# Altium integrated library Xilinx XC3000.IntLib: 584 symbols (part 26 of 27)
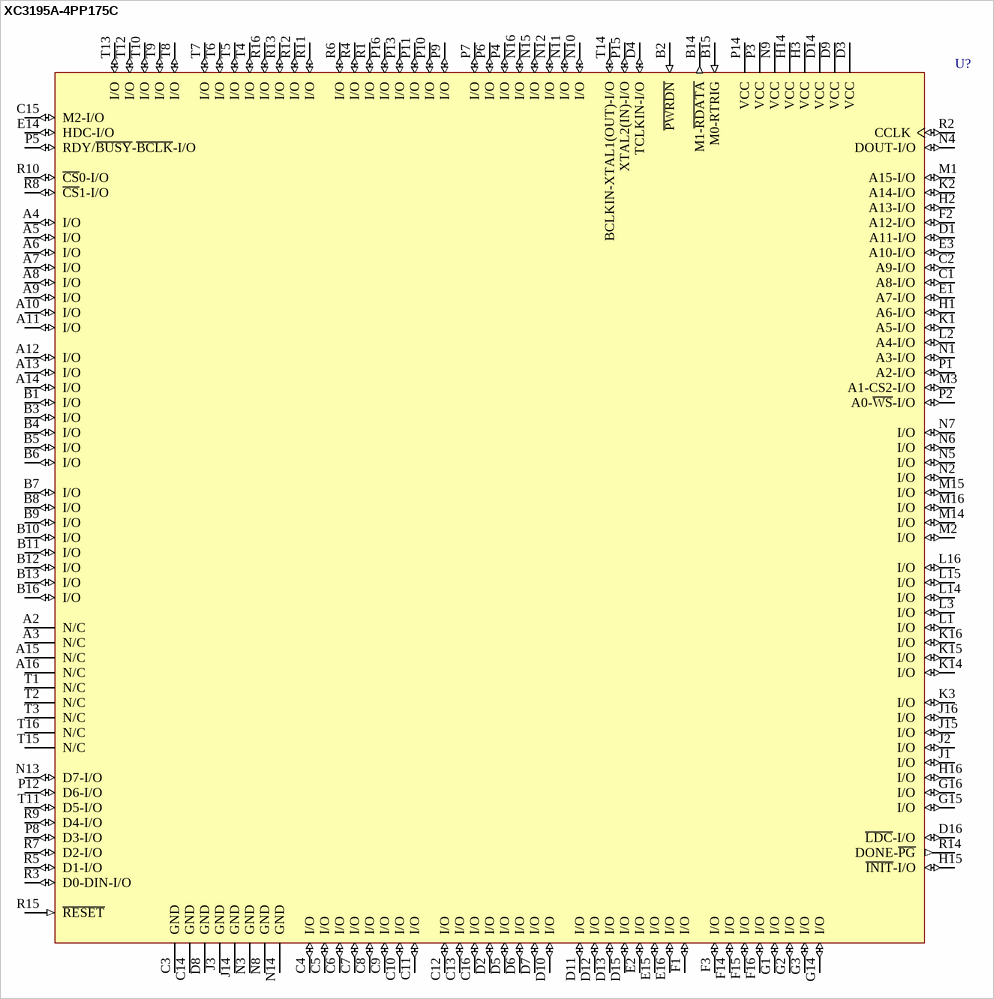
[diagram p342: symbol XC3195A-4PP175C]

## XC3195A-4PP175C
designator U?
Logic Cell Array with 484 CLBs, with 144 I/O Pins, 175-Pin PGA, Commercial Grade; ComponentAvailability: Not for New Design
footprint PP175 (PGA, 175-Leads, Body 42x42mm, Pitch 2.54mm)
3D model XC3195A-PP175 (175-Pin Plastic Pin Grid Array (PP175))
pins: A2 N/C, A3 N/C, A4 I/O (io), A5 I/O (io), A6 I/O (io), A7 I/O (io), A8 I/O (io), A9 I/O (io), A10 I/O (io), A11 I/O (io), A12 I/O (io), A13 I/O (io), A14 I/O (io), A15 N/C, A16 N/C, B1 I/O (io), B2 ~{PWRDN} (in), B3 I/O (io), B4 I/O (io), B5 I/O (io), B6 I/O (io), B7 I/O (io), B8 I/O (io), B9 I/O (io), B10 I/O (io), B11 I/O (io), B12 I/O (io), B13 I/O (io), B14 M1-~{RDATA} (out), B15 M0-RTRIG (in), B16 I/O (io), C1 A8-I/O (io), C2 A9-I/O (io), C3 GND (power), C4 I/O (io), C5 I/O (io), C6 I/O (io), C7 I/O (io), C8 I/O (io), C9 I/O (io), C10 I/O (io), C11 I/O (io), C12 I/O (io), C13 I/O (io), C14 GND (power), C15 M2-I/O (io), C16 I/O (io), D1 A11-I/O (io), D2 I/O (io), D3 VCC (power), D4 TCLKIN-I/O (io), D5 I/O (io), D6 I/O (io), D7 I/O (io), D8 GND (power), D9 VCC (power), D10 I/O (io), D11 I/O (io), D12 I/O (io), D13 I/O (io), D14 VCC (power), D15 I/O (io), D16 ~{LDC}-I/O (io), E1 A7-I/O (io), E2 I/O (io), E3 A10-I/O (io), E14 HDC-I/O (io), E15 I/O (io), E16 I/O (io), F1 I/O (io), F2 A12-I/O (io), F3 I/O (io), F14 I/O (io), F15 I/O (io), F16 I/O (io), G1 I/O (io), G2 I/O (io), G3 I/O (io), G14 I/O (io), G15 I/O (io), G16 I/O (io), H1 A6-I/O (io), H2 A13-I/O (io), H3 VCC (power), H14 VCC (power), H15 ~{INIT}-I/O (io), H16 I/O (io), J1 I/O (io), J2 I/O (io), J3 GND (power), J14 GND (power), J15 I/O (io), J16 I/O (io), K1 A5-I/O (io), K2 A14-I/O (io), K3 I/O (io), K14 I/O (io), K15 I/O (io), K16 I/O (io), L1 I/O (io), L2 A4-I/O (io), L3 I/O (io), L14 I/O (io), L15 I/O (io), L16 I/O (io), M1 A15-I/O (io), M2 I/O (io), M3 A1-CS2-I/O (io), M14 I/O (io), M15 I/O (io), M16 I/O (io), N1 A3-I/O (io), N2 I/O (io), N3 GND (power), N4 DOUT-I/O (io), N5 I/O (io), N6 I/O (io), N7 I/O (io), N8 GND (power), N9 VCC (power), N10 I/O (io), N11 I/O (io), N12 I/O (io), N13 D7-I/O (io), N14 GND (power), N15 I/O (io), N16 I/O (io), P1 A2-I/O (io), P2 A0-~{WS}-I/O (io), P3 VCC (power), P4 I/O (io), P5 RDY/~{BUSY}-~{BCLK}-I/O (io), P6 I/O (io), P7 I/O (io), P8 D3-I/O (io), P9 I/O (io), P10 I/O (io), P11 I/O (io), P12 D6-I/O (io), P13 I/O (io), P14 VCC (power), P15 XTAL2(IN)-I/O (io), P16 I/O (io), R1 I/O (io), R2 CCLK (io), R3 D0-DIN-I/O (io), R4 I/O (io), R5 D1-I/O (io), R6 I/O (io), R7 D2-I/O (io), R8 ~{CS}1-I/O (io), R9 D4-I/O (io), R10 ~{CS}0-I/O (io), R11 I/O (io), R12 I/O (io), R13 I/O (io), R14 DONE-~{PG} (out), R15 ~{RESET} (in), R16 I/O (io), T1 N/C, T2 N/C, T3 N/C, T4 I/O (io), T5 I/O (io), T6 I/O (io), T7 I/O (io), T8 I/O (io), T9 I/O (io), T10 I/O (io), T11 D5-I/O (io), T12 I/O (io), T13 I/O (io), T14 BCLKIN-XTAL1(OUT)-I/O (io), T15 N/C, T16 N/C

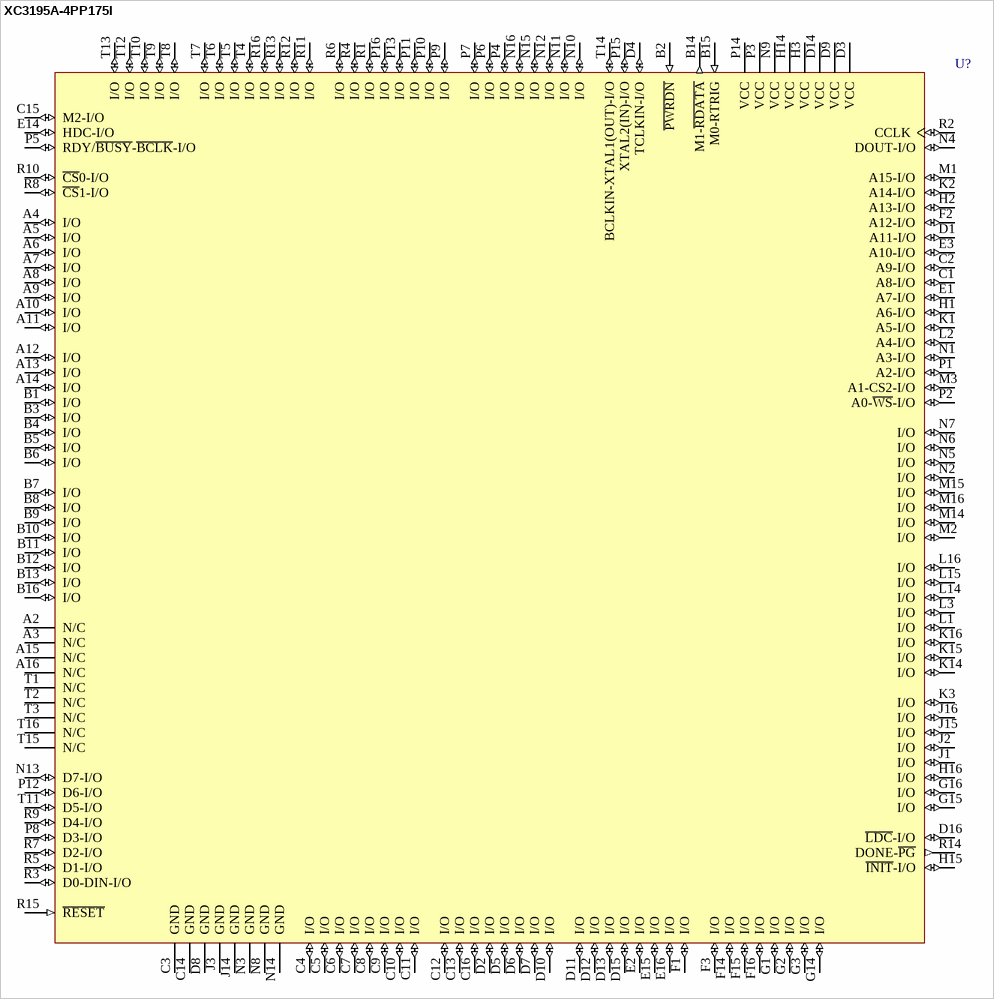
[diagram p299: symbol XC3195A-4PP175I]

## XC3195A-4PP175I
designator U?
Logic Cell Array with 484 CLBs, with 144 I/O Pins, 175-Pin PGA, Industrial Grade; ComponentAvailability: Not for New Design
footprint PP175 (PGA, 175-Leads, Body 42x42mm, Pitch 2.54mm)
3D model XC3195A-PP175 (175-Pin Plastic Pin Grid Array (PP175))
pins: A2 N/C, A3 N/C, A4 I/O (io), A5 I/O (io), A6 I/O (io), A7 I/O (io), A8 I/O (io), A9 I/O (io), A10 I/O (io), A11 I/O (io), A12 I/O (io), A13 I/O (io), A14 I/O (io), A15 N/C, A16 N/C, B1 I/O (io), B2 ~{PWRDN} (in), B3 I/O (io), B4 I/O (io), B5 I/O (io), B6 I/O (io), B7 I/O (io), B8 I/O (io), B9 I/O (io), B10 I/O (io), B11 I/O (io), B12 I/O (io), B13 I/O (io), B14 M1-~{RDATA} (out), B15 M0-RTRIG (in), B16 I/O (io), C1 A8-I/O (io), C2 A9-I/O (io), C3 GND (power), C4 I/O (io), C5 I/O (io), C6 I/O (io), C7 I/O (io), C8 I/O (io), C9 I/O (io), C10 I/O (io), C11 I/O (io), C12 I/O (io), C13 I/O (io), C14 GND (power), C15 M2-I/O (io), C16 I/O (io), D1 A11-I/O (io), D2 I/O (io), D3 VCC (power), D4 TCLKIN-I/O (io), D5 I/O (io), D6 I/O (io), D7 I/O (io), D8 GND (power), D9 VCC (power), D10 I/O (io), D11 I/O (io), D12 I/O (io), D13 I/O (io), D14 VCC (power), D15 I/O (io), D16 ~{LDC}-I/O (io), E1 A7-I/O (io), E2 I/O (io), E3 A10-I/O (io), E14 HDC-I/O (io), E15 I/O (io), E16 I/O (io), F1 I/O (io), F2 A12-I/O (io), F3 I/O (io), F14 I/O (io), F15 I/O (io), F16 I/O (io), G1 I/O (io), G2 I/O (io), G3 I/O (io), G14 I/O (io), G15 I/O (io), G16 I/O (io), H1 A6-I/O (io), H2 A13-I/O (io), H3 VCC (power), H14 VCC (power), H15 ~{INIT}-I/O (io), H16 I/O (io), J1 I/O (io), J2 I/O (io), J3 GND (power), J14 GND (power), J15 I/O (io), J16 I/O (io), K1 A5-I/O (io), K2 A14-I/O (io), K3 I/O (io), K14 I/O (io), K15 I/O (io), K16 I/O (io), L1 I/O (io), L2 A4-I/O (io), L3 I/O (io), L14 I/O (io), L15 I/O (io), L16 I/O (io), M1 A15-I/O (io), M2 I/O (io), M3 A1-CS2-I/O (io), M14 I/O (io), M15 I/O (io), M16 I/O (io), N1 A3-I/O (io), N2 I/O (io), N3 GND (power), N4 DOUT-I/O (io), N5 I/O (io), N6 I/O (io), N7 I/O (io), N8 GND (power), N9 VCC (power), N10 I/O (io), N11 I/O (io), N12 I/O (io), N13 D7-I/O (io), N14 GND (power), N15 I/O (io), N16 I/O (io), P1 A2-I/O (io), P2 A0-~{WS}-I/O (io), P3 VCC (power), P4 I/O (io), P5 RDY/~{BUSY}-~{BCLK}-I/O (io), P6 I/O (io), P7 I/O (io), P8 D3-I/O (io), P9 I/O (io), P10 I/O (io), P11 I/O (io), P12 D6-I/O (io), P13 I/O (io), P14 VCC (power), P15 XTAL2(IN)-I/O (io), P16 I/O (io), R1 I/O (io), R2 CCLK (io), R3 D0-DIN-I/O (io), R4 I/O (io), R5 D1-I/O (io), R6 I/O (io), R7 D2-I/O (io), R8 ~{CS}1-I/O (io), R9 D4-I/O (io), R10 ~{CS}0-I/O (io), R11 I/O (io), R12 I/O (io), R13 I/O (io), R14 DONE-~{PG} (out), R15 ~{RESET} (in), R16 I/O (io), T1 N/C, T2 N/C, T3 N/C, T4 I/O (io), T5 I/O (io), T6 I/O (io), T7 I/O (io), T8 I/O (io), T9 I/O (io), T10 I/O (io), T11 D5-I/O (io), T12 I/O (io), T13 I/O (io), T14 BCLKIN-XTAL1(OUT)-I/O (io), T15 N/C, T16 N/C

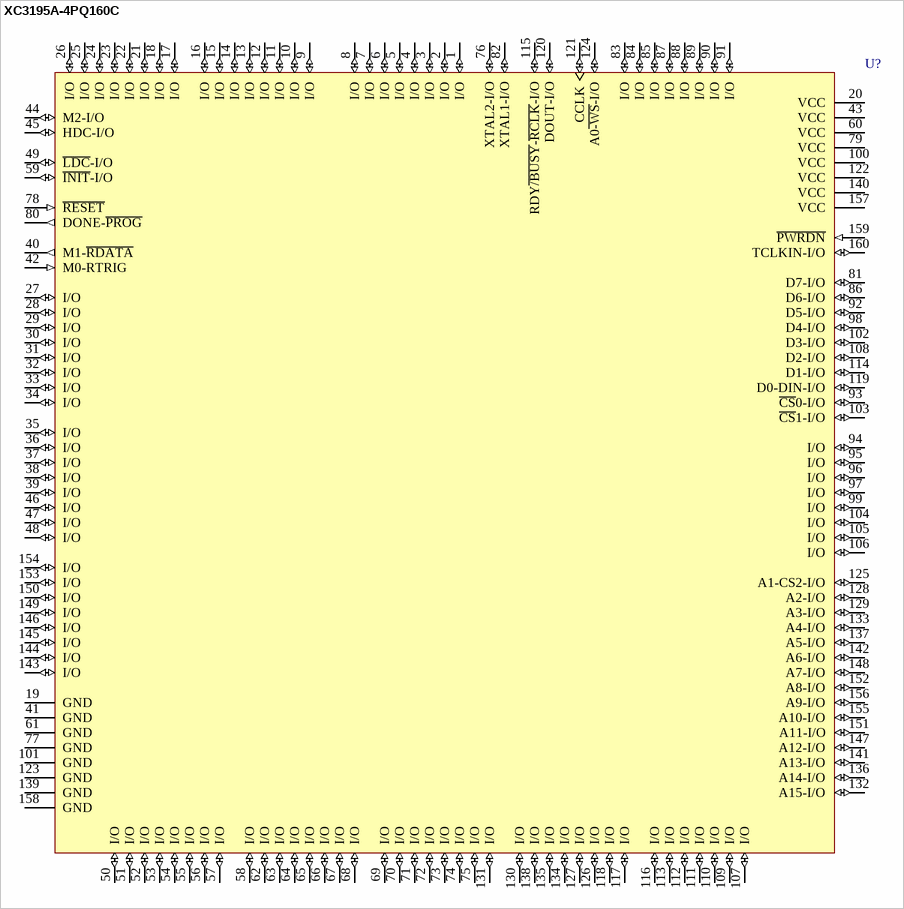
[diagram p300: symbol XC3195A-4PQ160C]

## XC3195A-4PQ160C
designator U?
Logic Cell Array with 484 CLBs, with 138 I/O Pins, 160-Pin PQFP, Commercial Grade; ComponentAvailability: Not for New Design
footprint PQ160_N (QFP, 160-Leads, Body 28 x 28mm, Pitch 0.65mm, IPC Medium Density)
footprint PQ160_L (QFP, 160-Leads, Body 28 x 28mm, Pitch 0.65mm, IPC High Density)
footprint PQ160_M (QFP, 160-Leads, Body 28 x 28mm, Pitch 0.65mm, IPC Low Density)
3D model XC3195A-PQ160 (160-Pin Plastic Quad Flat Pack (PQ160))
pins: 1 I/O (io), 2 I/O (io), 3 I/O (io), 4 I/O (io), 5 I/O (io), 6 I/O (io), 7 I/O (io), 8 I/O (io), 9 I/O (io), 10 I/O (io), 11 I/O (io), 12 I/O (io), 13 I/O (io), 14 I/O (io), 15 I/O (io), 16 I/O (io), 17 I/O (io), 18 I/O (io), 19 GND (power), 20 VCC (power), 21 I/O (io), 22 I/O (io), 23 I/O (io), 24 I/O (io), 25 I/O (io), 26 I/O (io), 27 I/O (io), 28 I/O (io), 29 I/O (io), 30 I/O (io), 31 I/O (io), 32 I/O (io), 33 I/O (io), 34 I/O (io), 35 I/O (io), 36 I/O (io), 37 I/O (io), 38 I/O (io), 39 I/O (io), 40 M1-~{RDATA} (out), 41 GND (power), 42 M0-RTRIG (in), 43 VCC (power), 44 M2-I/O (io), 45 HDC-I/O (io), 46 I/O (io), 47 I/O (io), 48 I/O (io), 49 ~{LDC}-I/O (io), 50 I/O (io), 51 I/O (io), 52 I/O (io), 53 I/O (io), 54 I/O (io), 55 I/O (io), 56 I/O (io), 57 I/O (io), 58 I/O (io), 59 ~{INIT}-I/O (io), 60 VCC (power), 61 GND (power), 62 I/O (io), 63 I/O (io), 64 I/O (io), 65 I/O (io), 66 I/O (io), 67 I/O (io), 68 I/O (io), 69 I/O (io), 70 I/O (io), 71 I/O (io), 72 I/O (io), 73 I/O (io), 74 I/O (io), 75 I/O (io), 76 XTAL2-I/O (io), 77 GND (power), 78 ~{RESET} (in), 79 VCC (power), 80 DONE-~{PROG} (out), 81 D7-I/O (io), 82 XTAL1-I/O (io), 83 I/O (io), 84 I/O (io), 85 I/O (io), 86 D6-I/O (io), 87 I/O (io), 88 I/O (io), 89 I/O (io), 90 I/O (io), 91 I/O (io), 92 D5-I/O (io), 93 ~{CS}0-I/O (io), 94 I/O (io), 95 I/O (io), 96 I/O (io), 97 I/O (io), 98 D4-I/O (io), 99 I/O (io), 100 VCC (power), 101 GND (power), 102 D3-I/O (io), 103 ~{CS}1-I/O (io), 104 I/O (io), 105 I/O (io), 106 I/O (io), 107 I/O (io), 108 D2-I/O (io), 109 I/O (io), 110 I/O (io), 111 I/O (io), 112 I/O (io), 113 I/O (io), 114 D1-I/O (io), 115 RDY~{/BUSY}-~{RCLK}-I/O (io), 116 I/O (io), 117 I/O (io), 118 I/O (io), 119 D0-DIN-I/O (io), 120 DOUT-I/O (io), 121 CCLK (io), 122 VCC (power), 123 GND (power), 124 A0~{-WS}-I/O (io), 125 A1-CS2-I/O (io), 126 I/O (io), 127 I/O (io), 128 A2-I/O (io), 129 A3-I/O (io), 130 I/O (io), 131 I/O (io), 132 A15-I/O (io), 133 A4-I/O (io), 134 I/O (io), 135 I/O (io), 136 A14-I/O (io), 137 A5-I/O (io), 138 I/O (io), 139 GND (power), 140 VCC (power), 141 A13-I/O (io), 142 A6-I/O (io), 143 I/O (io), 144 I/O (io), 145 I/O (io), 146 I/O (io), 147 A12-I/O (io), 148 A7-I/O (io), 149 I/O (io), 150 I/O (io), 151 A11-I/O (io), 152 A8-I/O (io), 153 I/O (io), 154 I/O (io), 155 A10-I/O (io), 156 A9-I/O (io), 157 VCC (power), 158 GND (power), 159 ~{PWRDN} (in), 160 TCLKIN-I/O (io)

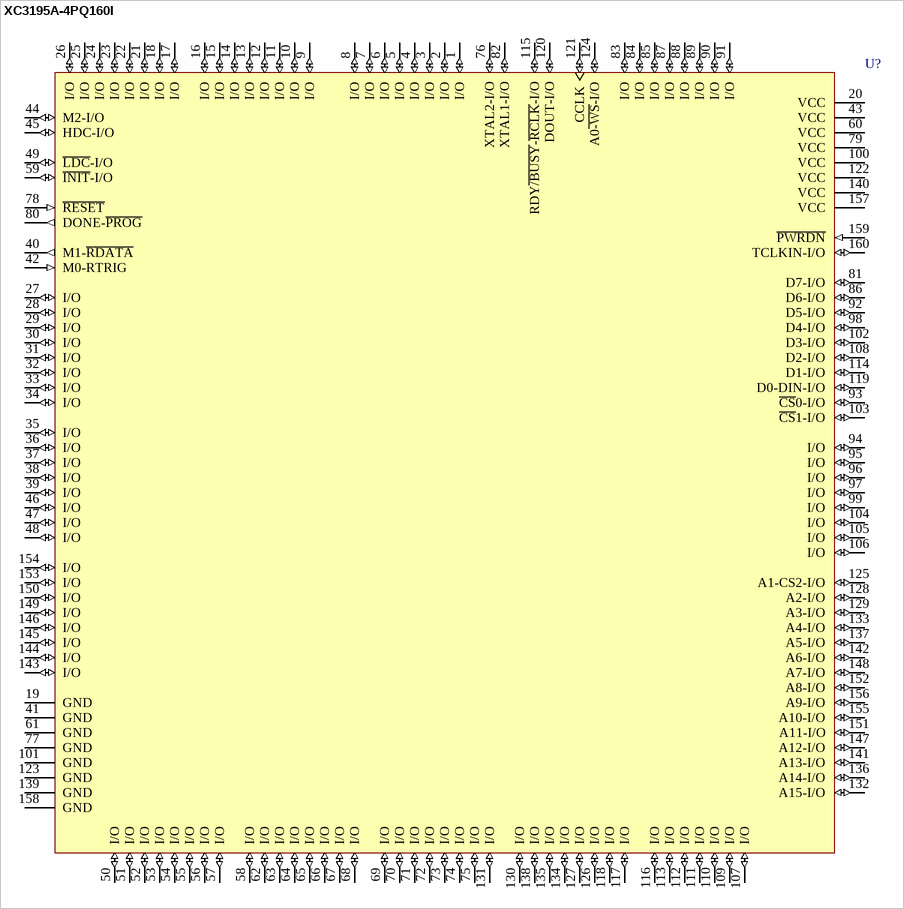
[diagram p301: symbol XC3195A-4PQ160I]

## XC3195A-4PQ160I
designator U?
Logic Cell Array with 484 CLBs, with 138 I/O Pins, 160-Pin PQFP, Industrial Grade; ComponentAvailability: Not for New Design
footprint PQ160_N (QFP, 160-Leads, Body 28 x 28mm, Pitch 0.65mm, IPC Medium Density)
footprint PQ160_L (QFP, 160-Leads, Body 28 x 28mm, Pitch 0.65mm, IPC High Density)
footprint PQ160_M (QFP, 160-Leads, Body 28 x 28mm, Pitch 0.65mm, IPC Low Density)
3D model XC3195A-PQ160 (160-Pin Plastic Quad Flat Pack (PQ160))
pins: 1 I/O (io), 2 I/O (io), 3 I/O (io), 4 I/O (io), 5 I/O (io), 6 I/O (io), 7 I/O (io), 8 I/O (io), 9 I/O (io), 10 I/O (io), 11 I/O (io), 12 I/O (io), 13 I/O (io), 14 I/O (io), 15 I/O (io), 16 I/O (io), 17 I/O (io), 18 I/O (io), 19 GND (power), 20 VCC (power), 21 I/O (io), 22 I/O (io), 23 I/O (io), 24 I/O (io), 25 I/O (io), 26 I/O (io), 27 I/O (io), 28 I/O (io), 29 I/O (io), 30 I/O (io), 31 I/O (io), 32 I/O (io), 33 I/O (io), 34 I/O (io), 35 I/O (io), 36 I/O (io), 37 I/O (io), 38 I/O (io), 39 I/O (io), 40 M1-~{RDATA} (out), 41 GND (power), 42 M0-RTRIG (in), 43 VCC (power), 44 M2-I/O (io), 45 HDC-I/O (io), 46 I/O (io), 47 I/O (io), 48 I/O (io), 49 ~{LDC}-I/O (io), 50 I/O (io), 51 I/O (io), 52 I/O (io), 53 I/O (io), 54 I/O (io), 55 I/O (io), 56 I/O (io), 57 I/O (io), 58 I/O (io), 59 ~{INIT}-I/O (io), 60 VCC (power), 61 GND (power), 62 I/O (io), 63 I/O (io), 64 I/O (io), 65 I/O (io), 66 I/O (io), 67 I/O (io), 68 I/O (io), 69 I/O (io), 70 I/O (io), 71 I/O (io), 72 I/O (io), 73 I/O (io), 74 I/O (io), 75 I/O (io), 76 XTAL2-I/O (io), 77 GND (power), 78 ~{RESET} (in), 79 VCC (power), 80 DONE-~{PROG} (out), 81 D7-I/O (io), 82 XTAL1-I/O (io), 83 I/O (io), 84 I/O (io), 85 I/O (io), 86 D6-I/O (io), 87 I/O (io), 88 I/O (io), 89 I/O (io), 90 I/O (io), 91 I/O (io), 92 D5-I/O (io), 93 ~{CS}0-I/O (io), 94 I/O (io), 95 I/O (io), 96 I/O (io), 97 I/O (io), 98 D4-I/O (io), 99 I/O (io), 100 VCC (power), 101 GND (power), 102 D3-I/O (io), 103 ~{CS}1-I/O (io), 104 I/O (io), 105 I/O (io), 106 I/O (io), 107 I/O (io), 108 D2-I/O (io), 109 I/O (io), 110 I/O (io), 111 I/O (io), 112 I/O (io), 113 I/O (io), 114 D1-I/O (io), 115 RDY~{/BUSY}-~{RCLK}-I/O (io), 116 I/O (io), 117 I/O (io), 118 I/O (io), 119 D0-DIN-I/O (io), 120 DOUT-I/O (io), 121 CCLK (io), 122 VCC (power), 123 GND (power), 124 A0~{-WS}-I/O (io), 125 A1-CS2-I/O (io), 126 I/O (io), 127 I/O (io), 128 A2-I/O (io), 129 A3-I/O (io), 130 I/O (io), 131 I/O (io), 132 A15-I/O (io), 133 A4-I/O (io), 134 I/O (io), 135 I/O (io), 136 A14-I/O (io), 137 A5-I/O (io), 138 I/O (io), 139 GND (power), 140 VCC (power), 141 A13-I/O (io), 142 A6-I/O (io), 143 I/O (io), 144 I/O (io), 145 I/O (io), 146 I/O (io), 147 A12-I/O (io), 148 A7-I/O (io), 149 I/O (io), 150 I/O (io), 151 A11-I/O (io), 152 A8-I/O (io), 153 I/O (io), 154 I/O (io), 155 A10-I/O (io), 156 A9-I/O (io), 157 VCC (power), 158 GND (power), 159 ~{PWRDN} (in), 160 TCLKIN-I/O (io)

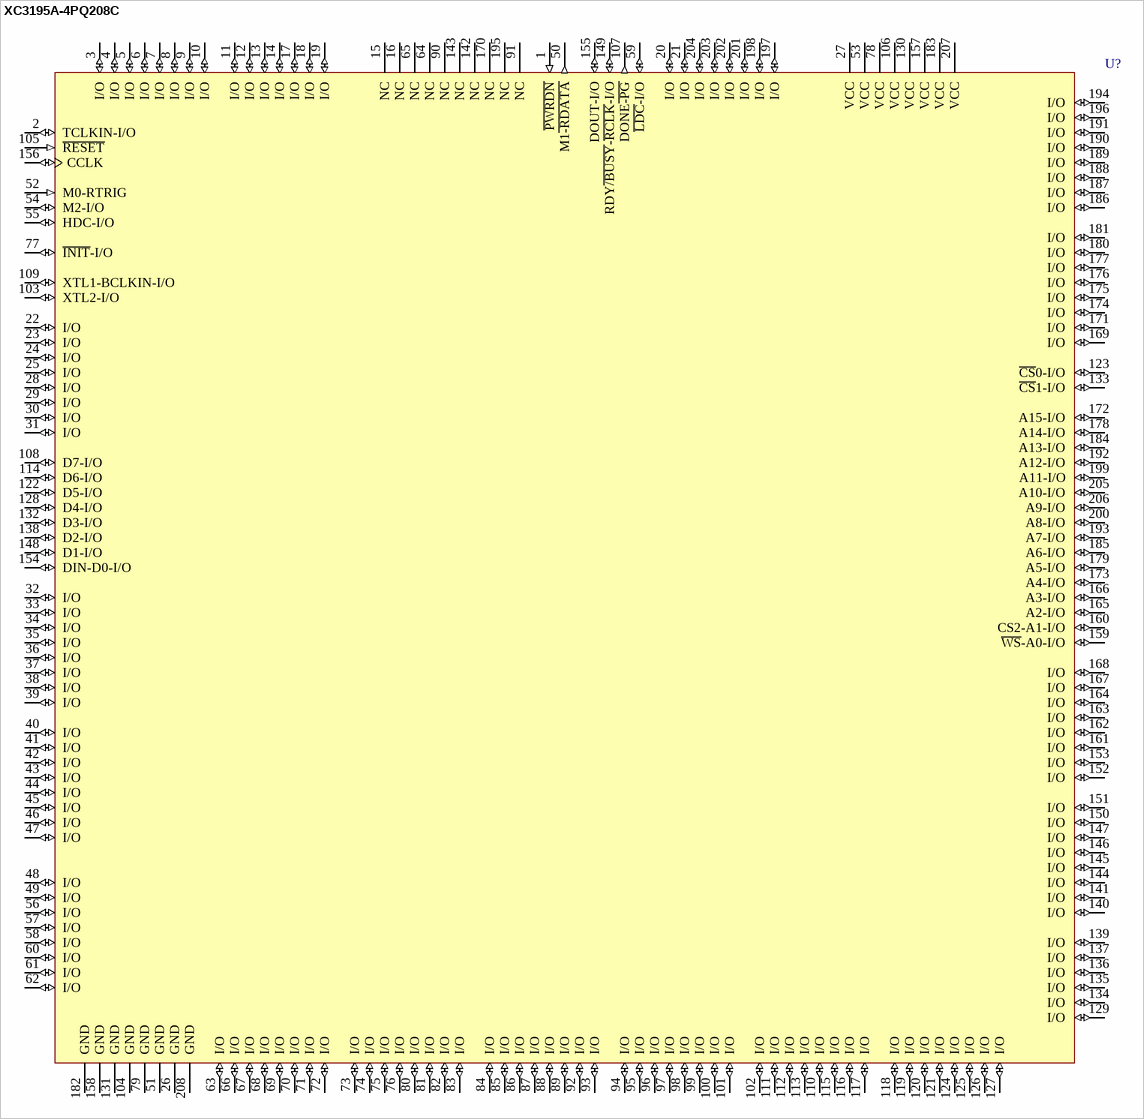
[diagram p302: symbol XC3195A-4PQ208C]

## XC3195A-4PQ208C
designator U?
Logic Cell Array with 484 CLBs, with 176 I/O Pins, 208-Pin PQFP, Commercial Grade; ComponentAvailability: Not for New Design
footprint PQ208_N (Shrink QFP, 208-Leads, Body 28x28mm, Pitch 0.5mm, IPC Medium Density)
footprint PQ208_L (Shrink QFP, 208-Leads, Body 28x28mm, Pitch 0.5mm, IPC High Density)
footprint PQ208_M (Shrink QFP, 208-Leads, Body 28x28mm, Pitch 0.5mm, IPC Low Density)
3D model XC3195A-PQ208 (208-Pin Plastic Quad Flat Pack (PQ208))
pins: 1 ~{PWRDN} (in), 2 TCLKIN-I/O (io), 3 I/O (io), 4 I/O (io), 5 I/O (io), 6 I/O (io), 7 I/O (io), 8 I/O (io), 9 I/O (io), 10 I/O (io), 11 I/O (io), 12 I/O (io), 13 I/O (io), 14 I/O (io), 15 NC, 16 NC, 17 I/O (io), 18 I/O (io), 19 I/O (io), 20 I/O (io), 21 I/O (io), 22 I/O (io), 23 I/O (io), 24 I/O (io), 25 I/O (io), 26 GND (power), 27 VCC (power), 28 I/O (io), 29 I/O (io), 30 I/O (io), 31 I/O (io), 32 I/O (io), 33 I/O (io), 34 I/O (io), 35 I/O (io), 36 I/O (io), 37 I/O (io), 38 I/O (io), 39 I/O (io), 40 I/O (io), 41 I/O (io), 42 I/O (io), 43 I/O (io), 44 I/O (io), 45 I/O (io), 46 I/O (io), 47 I/O (io), 48 I/O (io), 49 I/O (io), 50 M1~{-RDATA} (out), 51 GND (power), 52 M0-RTRIG (in), 53 VCC (power), 54 M2-I/O (io), 55 HDC-I/O (io), 56 I/O (io), 57 I/O (io), 58 I/O (io), 59 ~{LDC}-I/O (io), 60 I/O (io), 61 I/O (io), 62 I/O (io), 63 I/O (io), 64 NC, 65 NC, 66 I/O (io), 67 I/O (io), 68 I/O (io), 69 I/O (io), 70 I/O (io), 71 I/O (io), 72 I/O (io), 73 I/O (io), 74 I/O (io), 75 I/O (io), 76 I/O (io), 77 ~{INIT}-I/O (io), 78 VCC (power), 79 GND (power), 80 I/O (io), 81 I/O (io), 82 I/O (io), 83 I/O (io), 84 I/O (io), 85 I/O (io), 86 I/O (io), 87 I/O (io), 88 I/O (io), 89 I/O (io), 90 NC, 91 NC, 92 I/O (io), 93 I/O (io), 94 I/O (io), 95 I/O (io), 96 I/O (io), 97 I/O (io), 98 I/O (io), 99 I/O (io), 100 I/O (io), 101 I/O (io), 102 I/O (io), 103 XTL2-I/O (io), 104 GND (power), 105 ~{RESET} (in), 106 VCC (power), 107 DONE~{-PG} (out), 108 D7-I/O (io), 109 XTL1-BCLKIN-I/O (io), 110 I/O (io), 111 I/O (io), 112 I/O (io), 113 I/O (io), 114 D6-I/O (io), 115 I/O (io), 116 I/O (io), 117 I/O (io), 118 I/O (io), 119 I/O (io), 120 I/O (io), 121 I/O (io), 122 D5-I/O (io), 123 ~{CS}0-I/O (io), 124 I/O (io), 125 I/O (io), 126 I/O (io), 127 I/O (io), 128 D4-I/O (io), 129 I/O (io), 130 VCC (power), 131 GND (power), 132 D3-I/O (io), 133 ~{CS}1-I/O (io), 134 I/O (io), 135 I/O (io), 136 I/O (io), 137 I/O (io), 138 D2-I/O (io), 139 I/O (io), 140 I/O (io), 141 I/O (io), 142 NC, 143 NC, 144 I/O (io), 145 I/O (io), 146 I/O (io), 147 I/O (io), 148 D1-I/O (io), 149 RDY~{/BUSY}-~{RCLK}-I/O (io), 150 I/O (io), 151 I/O (io), 152 I/O (io), 153 I/O (io), 154 DIN-D0-I/O (io), 155 DOUT-I/O (io), 156 CCLK (io), 157 VCC (power), 158 GND (power), 159 ~{WS}-A0-I/O (io), 160 CS2-A1-I/O (io), 161 I/O (io), 162 I/O (io), 163 I/O (io), 164 I/O (io), 165 A2-I/O (io), 166 A3-I/O (io), 167 I/O (io), 168 I/O (io), 169 I/O (io), 170 NC, 171 I/O (io), 172 A15-I/O (io), 173 A4-I/O (io), 174 I/O (io), 175 I/O (io), 176 I/O (io), 177 I/O (io), 178 A14-I/O (io), 179 A5-I/O (io), 180 I/O (io), 181 I/O (io), 182 GND (power), 183 VCC (power), 184 A13-I/O (io), 185 A6-I/O (io), 186 I/O (io), 187 I/O (io), 188 I/O (io), 189 I/O (io), 190 I/O (io), 191 I/O (io), 192 A12-I/O (io), 193 A7-I/O (io), 194 I/O (io), 195 NC, 196 I/O (io), 197 I/O (io), 198 I/O (io), 199 A11-I/O (io), 200 A8-I/O (io), 201 I/O (io), 202 I/O (io), 203 I/O (io), 204 I/O (io), 205 A10-I/O (io), 206 A9-I/O (io), 207 VCC (power), 208 GND (power)

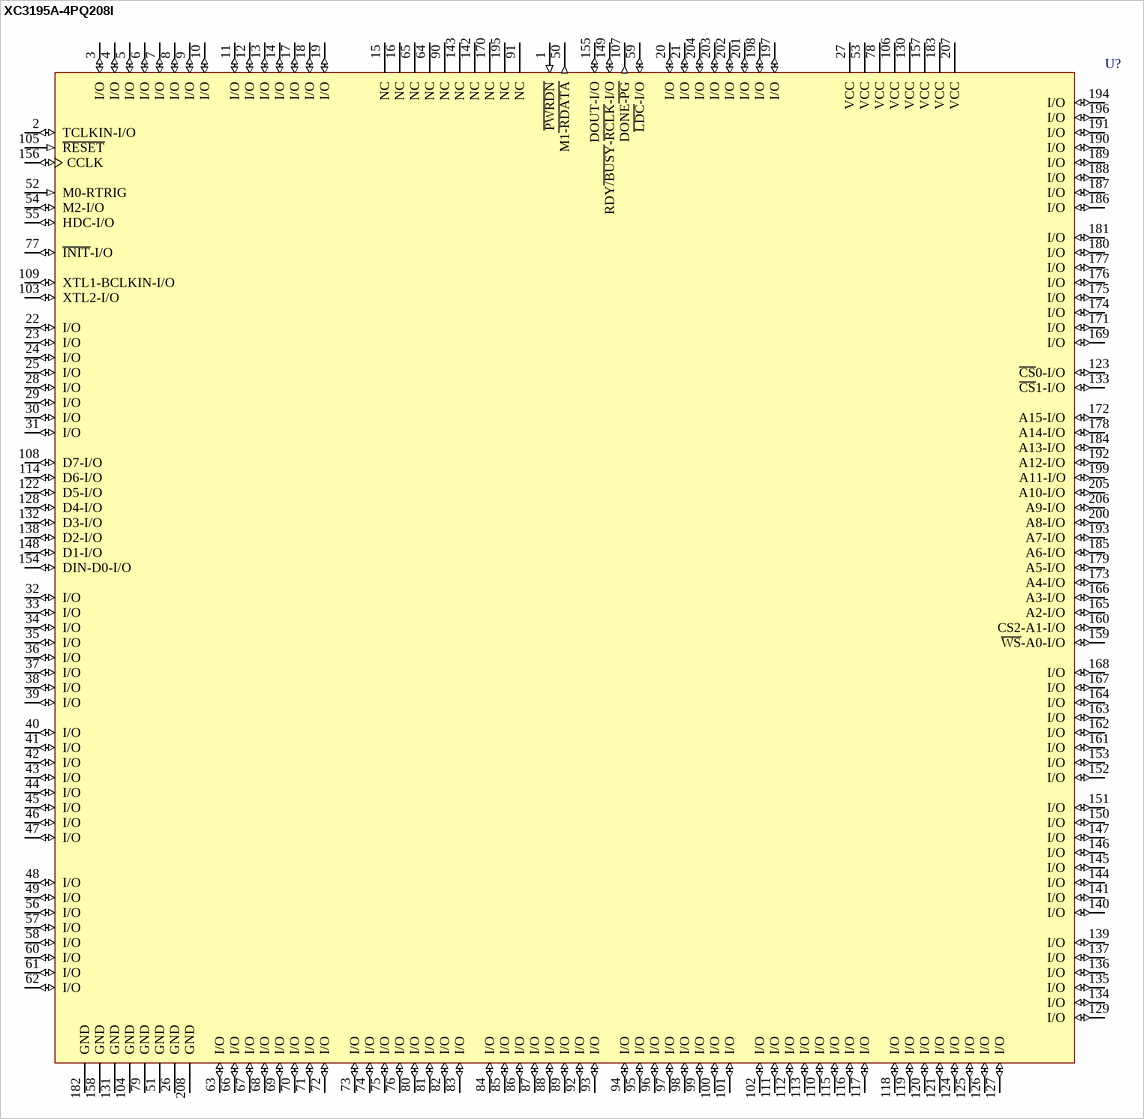
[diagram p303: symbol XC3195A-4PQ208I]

## XC3195A-4PQ208I
designator U?
Logic Cell Array with 484 CLBs, with 176 I/O Pins, 208-Pin PQFP, Industrial Grade; ComponentAvailability: Not for New Design
footprint PQ208_N (Shrink QFP, 208-Leads, Body 28x28mm, Pitch 0.5mm, IPC Medium Density)
footprint PQ208_L (Shrink QFP, 208-Leads, Body 28x28mm, Pitch 0.5mm, IPC High Density)
footprint PQ208_M (Shrink QFP, 208-Leads, Body 28x28mm, Pitch 0.5mm, IPC Low Density)
3D model XC3195A-PQ208 (208-Pin Plastic Quad Flat Pack (PQ208))
pins: 1 ~{PWRDN} (in), 2 TCLKIN-I/O (io), 3 I/O (io), 4 I/O (io), 5 I/O (io), 6 I/O (io), 7 I/O (io), 8 I/O (io), 9 I/O (io), 10 I/O (io), 11 I/O (io), 12 I/O (io), 13 I/O (io), 14 I/O (io), 15 NC, 16 NC, 17 I/O (io), 18 I/O (io), 19 I/O (io), 20 I/O (io), 21 I/O (io), 22 I/O (io), 23 I/O (io), 24 I/O (io), 25 I/O (io), 26 GND (power), 27 VCC (power), 28 I/O (io), 29 I/O (io), 30 I/O (io), 31 I/O (io), 32 I/O (io), 33 I/O (io), 34 I/O (io), 35 I/O (io), 36 I/O (io), 37 I/O (io), 38 I/O (io), 39 I/O (io), 40 I/O (io), 41 I/O (io), 42 I/O (io), 43 I/O (io), 44 I/O (io), 45 I/O (io), 46 I/O (io), 47 I/O (io), 48 I/O (io), 49 I/O (io), 50 M1~{-RDATA} (out), 51 GND (power), 52 M0-RTRIG (in), 53 VCC (power), 54 M2-I/O (io), 55 HDC-I/O (io), 56 I/O (io), 57 I/O (io), 58 I/O (io), 59 ~{LDC}-I/O (io), 60 I/O (io), 61 I/O (io), 62 I/O (io), 63 I/O (io), 64 NC, 65 NC, 66 I/O (io), 67 I/O (io), 68 I/O (io), 69 I/O (io), 70 I/O (io), 71 I/O (io), 72 I/O (io), 73 I/O (io), 74 I/O (io), 75 I/O (io), 76 I/O (io), 77 ~{INIT}-I/O (io), 78 VCC (power), 79 GND (power), 80 I/O (io), 81 I/O (io), 82 I/O (io), 83 I/O (io), 84 I/O (io), 85 I/O (io), 86 I/O (io), 87 I/O (io), 88 I/O (io), 89 I/O (io), 90 NC, 91 NC, 92 I/O (io), 93 I/O (io), 94 I/O (io), 95 I/O (io), 96 I/O (io), 97 I/O (io), 98 I/O (io), 99 I/O (io), 100 I/O (io), 101 I/O (io), 102 I/O (io), 103 XTL2-I/O (io), 104 GND (power), 105 ~{RESET} (in), 106 VCC (power), 107 DONE~{-PG} (out), 108 D7-I/O (io), 109 XTL1-BCLKIN-I/O (io), 110 I/O (io), 111 I/O (io), 112 I/O (io), 113 I/O (io), 114 D6-I/O (io), 115 I/O (io), 116 I/O (io), 117 I/O (io), 118 I/O (io), 119 I/O (io), 120 I/O (io), 121 I/O (io), 122 D5-I/O (io), 123 ~{CS}0-I/O (io), 124 I/O (io), 125 I/O (io), 126 I/O (io), 127 I/O (io), 128 D4-I/O (io), 129 I/O (io), 130 VCC (power), 131 GND (power), 132 D3-I/O (io), 133 ~{CS}1-I/O (io), 134 I/O (io), 135 I/O (io), 136 I/O (io), 137 I/O (io), 138 D2-I/O (io), 139 I/O (io), 140 I/O (io), 141 I/O (io), 142 NC, 143 NC, 144 I/O (io), 145 I/O (io), 146 I/O (io), 147 I/O (io), 148 D1-I/O (io), 149 RDY~{/BUSY}-~{RCLK}-I/O (io), 150 I/O (io), 151 I/O (io), 152 I/O (io), 153 I/O (io), 154 DIN-D0-I/O (io), 155 DOUT-I/O (io), 156 CCLK (io), 157 VCC (power), 158 GND (power), 159 ~{WS}-A0-I/O (io), 160 CS2-A1-I/O (io), 161 I/O (io), 162 I/O (io), 163 I/O (io), 164 I/O (io), 165 A2-I/O (io), 166 A3-I/O (io), 167 I/O (io), 168 I/O (io), 169 I/O (io), 170 NC, 171 I/O (io), 172 A15-I/O (io), 173 A4-I/O (io), 174 I/O (io), 175 I/O (io), 176 I/O (io), 177 I/O (io), 178 A14-I/O (io), 179 A5-I/O (io), 180 I/O (io), 181 I/O (io), 182 GND (power), 183 VCC (power), 184 A13-I/O (io), 185 A6-I/O (io), 186 I/O (io), 187 I/O (io), 188 I/O (io), 189 I/O (io), 190 I/O (io), 191 I/O (io), 192 A12-I/O (io), 193 A7-I/O (io), 194 I/O (io), 195 NC, 196 I/O (io), 197 I/O (io), 198 I/O (io), 199 A11-I/O (io), 200 A8-I/O (io), 201 I/O (io), 202 I/O (io), 203 I/O (io), 204 I/O (io), 205 A10-I/O (io), 206 A9-I/O (io), 207 VCC (power), 208 GND (power)

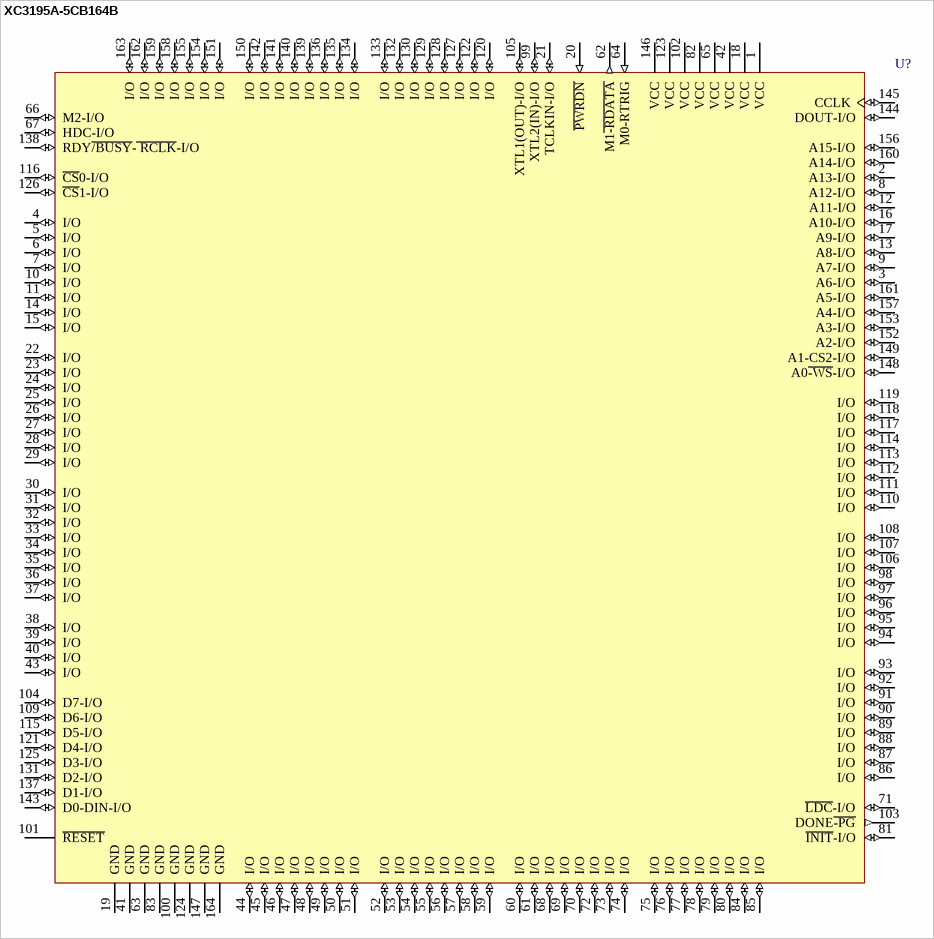
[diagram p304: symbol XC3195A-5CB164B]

## XC3195A-5CB164B
designator U?
Logic Cell Array with 484 CLBs, with 142 I/O Pins, 164-Pin CQFP, Military Class B Grade; ComponentAvailability: Not for New Design
footprint CB164_N (CQFP, 164-Leads, Body 29x29mm; Pitch 0.635mm, Gullwing Leadform, IPC Medium Density)
footprint CB164_L (CQFP, 164-Leads, Body 29x29mm; Pitch 0.635mm, Gullwing Leadform, IPC High Density)
footprint CB164_M (CQFP, 164-Leads, Body 29x29mm; Pitch 0.635mm, Gullwing Leadform, IPC Low Density)
3D model XC3195A-CB164 (164-Pin Ceramic Brazed Quad Flat Pack (CB164))
pins: 1 VCC (power), 2 A13-I/O (io), 3 A6-I/O (io), 4 I/O (io), 5 I/O (io), 6 I/O (io), 7 I/O (io), 8 A12-I/O (io), 9 A7-I/O (io), 10 I/O (io), 11 I/O (io), 12 A11-I/O (io), 13 A8-I/O (io), 14 I/O (io), 15 I/O (io), 16 A10-I/O (io), 17 A9-I/O (io), 18 VCC (power), 19 GND (power), 20 ~{PWRDN} (in), 21 TCLKIN-I/O (io), 22 I/O (io), 23 I/O (io), 24 I/O (io), 25 I/O (io), 26 I/O (io), 27 I/O (io), 28 I/O (io), 29 I/O (io), 30 I/O (io), 31 I/O (io), 32 I/O (io), 33 I/O (io), 34 I/O (io), 35 I/O (io), 36 I/O (io), 37 I/O (io), 38 I/O (io), 39 I/O (io), 40 I/O (io), 41 GND (power), 42 VCC (power), 43 I/O (io), 44 I/O (io), 45 I/O (io), 46 I/O (io), 47 I/O (io), 48 I/O (io), 49 I/O (io), 50 I/O (io), 51 I/O (io), 52 I/O (io), 53 I/O (io), 54 I/O (io), 55 I/O (io), 56 I/O (io), 57 I/O (io), 58 I/O (io), 59 I/O (io), 60 I/O (io), 61 I/O (io), 62 M1~{-RDATA} (out), 63 GND (power), 64 M0-RTRIG (in), 65 VCC (power), 66 M2-I/O (io), 67 HDC-I/O (io), 68 I/O (io), 69 I/O (io), 70 I/O (io), 71 ~{LDC}-I/O (io), 72 I/O (io), 73 I/O (io), 74 I/O (io), 75 I/O (io), 76 I/O (io), 77 I/O (io), 78 I/O (io), 79 I/O (io), 80 I/O (io), 81 ~{INIT}-I/O (io), 82 VCC (power), 83 GND (power), 84 I/O (io), 85 I/O (io), 86 I/O (io), 87 I/O (io), 88 I/O (io), 89 I/O (io), 90 I/O (io), 91 I/O (io), 92 I/O (io), 93 I/O (io), 94 I/O (io), 95 I/O (io), 96 I/O (io), 97 I/O (io), 98 I/O (io), 99 XTL2(IN)-I/O (io), 100 GND (power), 101 ~{RESET} (oe), 102 VCC (power), 103 DONE~{-PG} (out), 104 D7-I/O (io), 105 XTL1(OUT)-I/O (io), 106 I/O (io), 107 I/O (io), 108 I/O (io), 109 D6-I/O (io), 110 I/O (io), 111 I/O (io), 112 I/O (io), 113 I/O (io), 114 I/O (io), 115 D5-I/O (io), 116 ~{CS}0-I/O (io), 117 I/O (io), 118 I/O (io), 119 I/O (io), 120 I/O (io), 121 D4-I/O (io), 122 I/O (io), 123 VCC (power), 124 GND (power), 125 D3-I/O (io), 126 ~{CS}1-I/O (io), 127 I/O (io), 128 I/O (io), 129 I/O (io), 130 I/O (io), 131 D2-I/O (io), 132 I/O (io), 133 I/O (io), 134 I/O (io), 135 I/O (io), 136 I/O (io), 137 D1-I/O (io), 138 RDY~{/BUSY}-~{ RCLK}-I/O (io), 139 I/O (io), 140 I/O (io), 141 I/O (io), 142 I/O (io), 143 D0-DIN-I/O (io), 144 DOUT-I/O (io), 145 CCLK (io), 146 VCC (power), 147 GND (power), 148 A0~{-WS}-I/O (io), 149 A1-CS2-I/O (io), 150 I/O (io), 151 I/O (io), 152 A2-I/O (io), 153 A3-I/O (io), 154 I/O (io), 155 I/O (io), 156 A15-I/O (io), 157 A4-I/O (io), 158 I/O (io), 159 I/O (io), 160 A14-I/O (io), 161 A5-I/O (io), 162 I/O (io), 163 I/O (io), 164 GND (power)

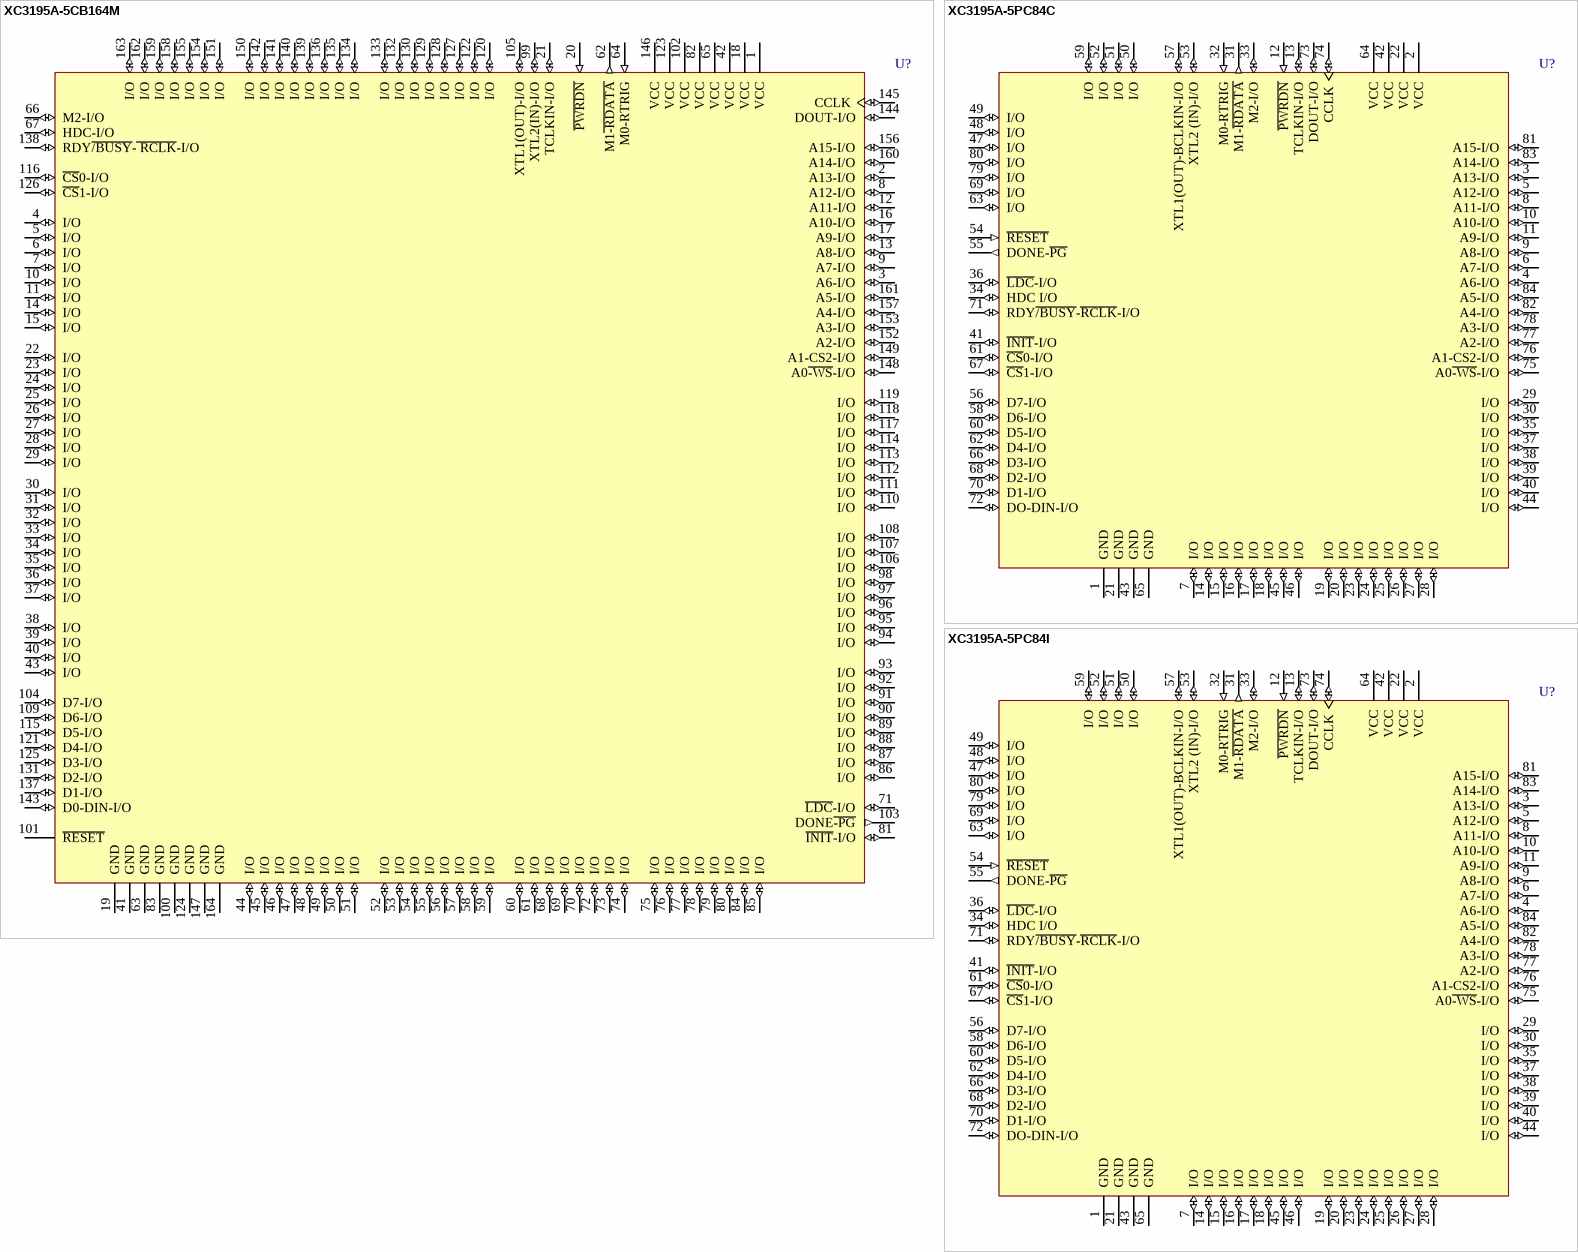
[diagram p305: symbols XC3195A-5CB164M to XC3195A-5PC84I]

## XC3195A-5CB164M
designator U?
Logic Cell Array with 484 CLBs, with 142 I/O Pins, 164-Pin CQFP, Military Grade; ComponentAvailability: Not for New Design
footprint CB164_N (CQFP, 164-Leads, Body 29x29mm; Pitch 0.635mm, Gullwing Leadform, IPC Medium Density)
footprint CB164_L (CQFP, 164-Leads, Body 29x29mm; Pitch 0.635mm, Gullwing Leadform, IPC High Density)
footprint CB164_M (CQFP, 164-Leads, Body 29x29mm; Pitch 0.635mm, Gullwing Leadform, IPC Low Density)
3D model XC3195A-CB164 (164-Pin Ceramic Brazed Quad Flat Pack (CB164))
pins: 1 VCC (power), 2 A13-I/O (io), 3 A6-I/O (io), 4 I/O (io), 5 I/O (io), 6 I/O (io), 7 I/O (io), 8 A12-I/O (io), 9 A7-I/O (io), 10 I/O (io), 11 I/O (io), 12 A11-I/O (io), 13 A8-I/O (io), 14 I/O (io), 15 I/O (io), 16 A10-I/O (io), 17 A9-I/O (io), 18 VCC (power), 19 GND (power), 20 ~{PWRDN} (in), 21 TCLKIN-I/O (io), 22 I/O (io), 23 I/O (io), 24 I/O (io), 25 I/O (io), 26 I/O (io), 27 I/O (io), 28 I/O (io), 29 I/O (io), 30 I/O (io), 31 I/O (io), 32 I/O (io), 33 I/O (io), 34 I/O (io), 35 I/O (io), 36 I/O (io), 37 I/O (io), 38 I/O (io), 39 I/O (io), 40 I/O (io), 41 GND (power), 42 VCC (power), 43 I/O (io), 44 I/O (io), 45 I/O (io), 46 I/O (io), 47 I/O (io), 48 I/O (io), 49 I/O (io), 50 I/O (io), 51 I/O (io), 52 I/O (io), 53 I/O (io), 54 I/O (io), 55 I/O (io), 56 I/O (io), 57 I/O (io), 58 I/O (io), 59 I/O (io), 60 I/O (io), 61 I/O (io), 62 M1~{-RDATA} (out), 63 GND (power), 64 M0-RTRIG (in), 65 VCC (power), 66 M2-I/O (io), 67 HDC-I/O (io), 68 I/O (io), 69 I/O (io), 70 I/O (io), 71 ~{LDC}-I/O (io), 72 I/O (io), 73 I/O (io), 74 I/O (io), 75 I/O (io), 76 I/O (io), 77 I/O (io), 78 I/O (io), 79 I/O (io), 80 I/O (io), 81 ~{INIT}-I/O (io), 82 VCC (power), 83 GND (power), 84 I/O (io), 85 I/O (io), 86 I/O (io), 87 I/O (io), 88 I/O (io), 89 I/O (io), 90 I/O (io), 91 I/O (io), 92 I/O (io), 93 I/O (io), 94 I/O (io), 95 I/O (io), 96 I/O (io), 97 I/O (io), 98 I/O (io), 99 XTL2(IN)-I/O (io), 100 GND (power), 101 ~{RESET} (oe), 102 VCC (power), 103 DONE~{-PG} (out), 104 D7-I/O (io), 105 XTL1(OUT)-I/O (io), 106 I/O (io), 107 I/O (io), 108 I/O (io), 109 D6-I/O (io), 110 I/O (io), 111 I/O (io), 112 I/O (io), 113 I/O (io), 114 I/O (io), 115 D5-I/O (io), 116 ~{CS}0-I/O (io), 117 I/O (io), 118 I/O (io), 119 I/O (io), 120 I/O (io), 121 D4-I/O (io), 122 I/O (io), 123 VCC (power), 124 GND (power), 125 D3-I/O (io), 126 ~{CS}1-I/O (io), 127 I/O (io), 128 I/O (io), 129 I/O (io), 130 I/O (io), 131 D2-I/O (io), 132 I/O (io), 133 I/O (io), 134 I/O (io), 135 I/O (io), 136 I/O (io), 137 D1-I/O (io), 138 RDY~{/BUSY}-~{ RCLK}-I/O (io), 139 I/O (io), 140 I/O (io), 141 I/O (io), 142 I/O (io), 143 D0-DIN-I/O (io), 144 DOUT-I/O (io), 145 CCLK (io), 146 VCC (power), 147 GND (power), 148 A0~{-WS}-I/O (io), 149 A1-CS2-I/O (io), 150 I/O (io), 151 I/O (io), 152 A2-I/O (io), 153 A3-I/O (io), 154 I/O (io), 155 I/O (io), 156 A15-I/O (io), 157 A4-I/O (io), 158 I/O (io), 159 I/O (io), 160 A14-I/O (io), 161 A5-I/O (io), 162 I/O (io), 163 I/O (io), 164 GND (power)

## XC3195A-5PC84C
designator U?
Logic Cell Array with 484 CLBs, with 70 I/O Pins, 84-Pin PLCC, Commercial Grade; ComponentAvailability: Not for New Design
footprint PC84_N (Leaded Chip Carrier, 84-Leads, Body 29.3x29.3mm, Pitch 1.27mm, IPC Medium Density)
footprint PC84_L (Leaded Chip Carrier, 84-Leads, Body 29.3x29.3mm, Pitch 1.27mm, IPC High Density)
footprint PC84_M (Leaded Chip Carrier, 84-Leads, Body 29.3x29.3mm, Pitch 1.27mm, IPC Low Density)
3D model XC3195A-PC84 (84-Pin Plastic Leaded Chip Carrier (PC84))
pins: 1 GND (power), 2 VCC (power), 3 A13-I/O (io), 4 A6-I/O (io), 5 A12-I/O (io), 6 A7-I/O (io), 7 I/O (io), 8 A11-I/O (io), 9 A8-I/O (io), 10 A10-I/O (io), 11 A9-I/O (io), 12 ~{PWRDN} (in), 13 TCLKIN-I/O (io), 14 I/O (io), 15 I/O (io), 16 I/O (io), 17 I/O (io), 18 I/O (io), 19 I/O (io), 20 I/O (io), 21 GND (power), 22 VCC (power), 23 I/O (io), 24 I/O (io), 25 I/O (io), 26 I/O (io), 27 I/O (io), 28 I/O (io), 29 I/O (io), 30 I/O (io), 31 M1-~{RDATA} (out), 32 M0-RTRIG (in), 33 M2-I/O (io), 34 HDC I/O (io), 35 I/O (io), 36 ~{LDC}-I/O (io), 37 I/O (io), 38 I/O (io), 39 I/O (io), 40 I/O (io), 41 ~{INIT}-I/O (io), 42 VCC (power), 43 GND (power), 44 I/O (io), 45 I/O (io), 46 I/O (io), 47 I/O (io), 48 I/O (io), 49 I/O (io), 50 I/O (io), 51 I/O (io), 52 I/O (io), 53 XTL2 (IN)-I/O (io), 54 ~{RESET} (in), 55 DONE-~{PG} (out), 56 D7-I/O (io), 57 XTL1(OUT)-BCLKIN-I/O (io), 58 D6-I/O (io), 59 I/O (io), 60 D5-I/O (io), 61 ~{CS}0-I/O (io), 62 D4-I/O (io), 63 I/O (io), 64 VCC (power), 65 GND (power), 66 D3-I/O (io), 67 ~{CS}1-I/O (io), 68 D2-I/O (io), 69 I/O (io), 70 D1-I/O (io), 71 RDY~{/BUSY}-~{RCLK}-I/O (io), 72 DO-DIN-I/O (io), 73 DOUT-I/O (io), 74 CCLK (io), 75 A0~{-WS}-I/O (io), 76 A1-CS2-I/O (io), 77 A2-I/O (io), 78 A3-I/O (io), 79 I/O (io), 80 I/O (io), 81 A15-I/O (io), 82 A4-I/O (io), 83 A14-I/O (io), 84 A5-I/O (io)

## XC3195A-5PC84I
designator U?
Logic Cell Array with 484 CLBs, with 70 I/O Pins, 84-Pin PLCC, Industrial Grade; ComponentAvailability: Not for New Design
footprint PC84_N (Leaded Chip Carrier, 84-Leads, Body 29.3x29.3mm, Pitch 1.27mm, IPC Medium Density)
footprint PC84_L (Leaded Chip Carrier, 84-Leads, Body 29.3x29.3mm, Pitch 1.27mm, IPC High Density)
footprint PC84_M (Leaded Chip Carrier, 84-Leads, Body 29.3x29.3mm, Pitch 1.27mm, IPC Low Density)
3D model XC3195A-PC84 (84-Pin Plastic Leaded Chip Carrier (PC84))
pins: 1 GND (power), 2 VCC (power), 3 A13-I/O (io), 4 A6-I/O (io), 5 A12-I/O (io), 6 A7-I/O (io), 7 I/O (io), 8 A11-I/O (io), 9 A8-I/O (io), 10 A10-I/O (io), 11 A9-I/O (io), 12 ~{PWRDN} (in), 13 TCLKIN-I/O (io), 14 I/O (io), 15 I/O (io), 16 I/O (io), 17 I/O (io), 18 I/O (io), 19 I/O (io), 20 I/O (io), 21 GND (power), 22 VCC (power), 23 I/O (io), 24 I/O (io), 25 I/O (io), 26 I/O (io), 27 I/O (io), 28 I/O (io), 29 I/O (io), 30 I/O (io), 31 M1-~{RDATA} (out), 32 M0-RTRIG (in), 33 M2-I/O (io), 34 HDC I/O (io), 35 I/O (io), 36 ~{LDC}-I/O (io), 37 I/O (io), 38 I/O (io), 39 I/O (io), 40 I/O (io), 41 ~{INIT}-I/O (io), 42 VCC (power), 43 GND (power), 44 I/O (io), 45 I/O (io), 46 I/O (io), 47 I/O (io), 48 I/O (io), 49 I/O (io), 50 I/O (io), 51 I/O (io), 52 I/O (io), 53 XTL2 (IN)-I/O (io), 54 ~{RESET} (in), 55 DONE-~{PG} (out), 56 D7-I/O (io), 57 XTL1(OUT)-BCLKIN-I/O (io), 58 D6-I/O (io), 59 I/O (io), 60 D5-I/O (io), 61 ~{CS}0-I/O (io), 62 D4-I/O (io), 63 I/O (io), 64 VCC (power), 65 GND (power), 66 D3-I/O (io), 67 ~{CS}1-I/O (io), 68 D2-I/O (io), 69 I/O (io), 70 D1-I/O (io), 71 RDY~{/BUSY}-~{RCLK}-I/O (io), 72 DO-DIN-I/O (io), 73 DOUT-I/O (io), 74 CCLK (io), 75 A0~{-WS}-I/O (io), 76 A1-CS2-I/O (io), 77 A2-I/O (io), 78 A3-I/O (io), 79 I/O (io), 80 I/O (io), 81 A15-I/O (io), 82 A4-I/O (io), 83 A14-I/O (io), 84 A5-I/O (io)

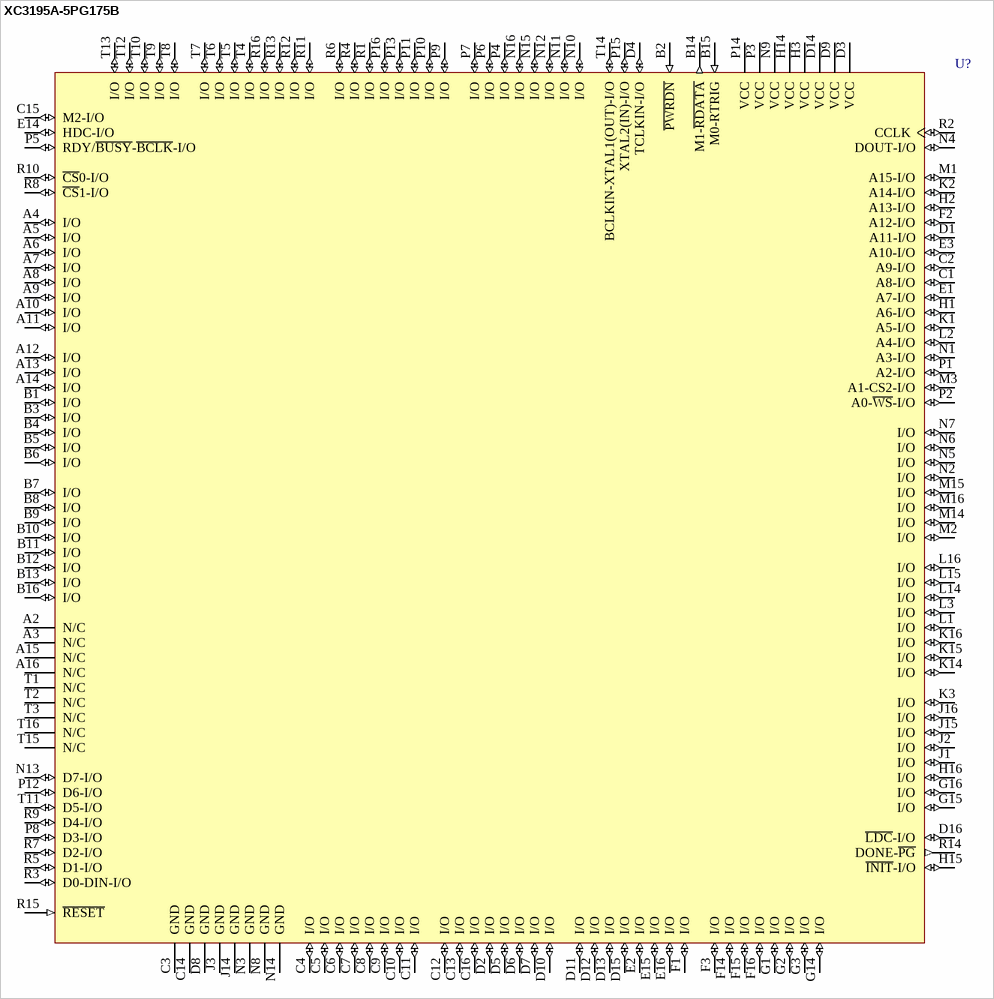
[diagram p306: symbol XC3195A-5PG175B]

## XC3195A-5PG175B
designator U?
Logic Cell Array with 484 CLBs, with 144 I/O Pins, 175-Pin PGA, Military Class B Grade; ComponentAvailability: Not for New Design
footprint PG175 (PGA, 175-Leads, Body 42x42mm, Pitch 2.54mm)
3D model XC3195A-PG175 (175-Pin Ceramic Pin Grid Array (PG175))
pins: A2 N/C, A3 N/C, A4 I/O (io), A5 I/O (io), A6 I/O (io), A7 I/O (io), A8 I/O (io), A9 I/O (io), A10 I/O (io), A11 I/O (io), A12 I/O (io), A13 I/O (io), A14 I/O (io), A15 N/C, A16 N/C, B1 I/O (io), B2 ~{PWRDN} (in), B3 I/O (io), B4 I/O (io), B5 I/O (io), B6 I/O (io), B7 I/O (io), B8 I/O (io), B9 I/O (io), B10 I/O (io), B11 I/O (io), B12 I/O (io), B13 I/O (io), B14 M1-~{RDATA} (out), B15 M0-RTRIG (in), B16 I/O (io), C1 A8-I/O (io), C2 A9-I/O (io), C3 GND (power), C4 I/O (io), C5 I/O (io), C6 I/O (io), C7 I/O (io), C8 I/O (io), C9 I/O (io), C10 I/O (io), C11 I/O (io), C12 I/O (io), C13 I/O (io), C14 GND (power), C15 M2-I/O (io), C16 I/O (io), D1 A11-I/O (io), D2 I/O (io), D3 VCC (power), D4 TCLKIN-I/O (io), D5 I/O (io), D6 I/O (io), D7 I/O (io), D8 GND (power), D9 VCC (power), D10 I/O (io), D11 I/O (io), D12 I/O (io), D13 I/O (io), D14 VCC (power), D15 I/O (io), D16 ~{LDC}-I/O (io), E1 A7-I/O (io), E2 I/O (io), E3 A10-I/O (io), E14 HDC-I/O (io), E15 I/O (io), E16 I/O (io), F1 I/O (io), F2 A12-I/O (io), F3 I/O (io), F14 I/O (io), F15 I/O (io), F16 I/O (io), G1 I/O (io), G2 I/O (io), G3 I/O (io), G14 I/O (io), G15 I/O (io), G16 I/O (io), H1 A6-I/O (io), H2 A13-I/O (io), H3 VCC (power), H14 VCC (power), H15 ~{INIT}-I/O (io), H16 I/O (io), J1 I/O (io), J2 I/O (io), J3 GND (power), J14 GND (power), J15 I/O (io), J16 I/O (io), K1 A5-I/O (io), K2 A14-I/O (io), K3 I/O (io), K14 I/O (io), K15 I/O (io), K16 I/O (io), L1 I/O (io), L2 A4-I/O (io), L3 I/O (io), L14 I/O (io), L15 I/O (io), L16 I/O (io), M1 A15-I/O (io), M2 I/O (io), M3 A1-CS2-I/O (io), M14 I/O (io), M15 I/O (io), M16 I/O (io), N1 A3-I/O (io), N2 I/O (io), N3 GND (power), N4 DOUT-I/O (io), N5 I/O (io), N6 I/O (io), N7 I/O (io), N8 GND (power), N9 VCC (power), N10 I/O (io), N11 I/O (io), N12 I/O (io), N13 D7-I/O (io), N14 GND (power), N15 I/O (io), N16 I/O (io), P1 A2-I/O (io), P2 A0-~{WS}-I/O (io), P3 VCC (power), P4 I/O (io), P5 RDY/~{BUSY}-~{BCLK}-I/O (io), P6 I/O (io), P7 I/O (io), P8 D3-I/O (io), P9 I/O (io), P10 I/O (io), P11 I/O (io), P12 D6-I/O (io), P13 I/O (io), P14 VCC (power), P15 XTAL2(IN)-I/O (io), P16 I/O (io), R1 I/O (io), R2 CCLK (io), R3 D0-DIN-I/O (io), R4 I/O (io), R5 D1-I/O (io), R6 I/O (io), R7 D2-I/O (io), R8 ~{CS}1-I/O (io), R9 D4-I/O (io), R10 ~{CS}0-I/O (io), R11 I/O (io), R12 I/O (io), R13 I/O (io), R14 DONE-~{PG} (out), R15 ~{RESET} (in), R16 I/O (io), T1 N/C, T2 N/C, T3 N/C, T4 I/O (io), T5 I/O (io), T6 I/O (io), T7 I/O (io), T8 I/O (io), T9 I/O (io), T10 I/O (io), T11 D5-I/O (io), T12 I/O (io), T13 I/O (io), T14 BCLKIN-XTAL1(OUT)-I/O (io), T15 N/C, T16 N/C

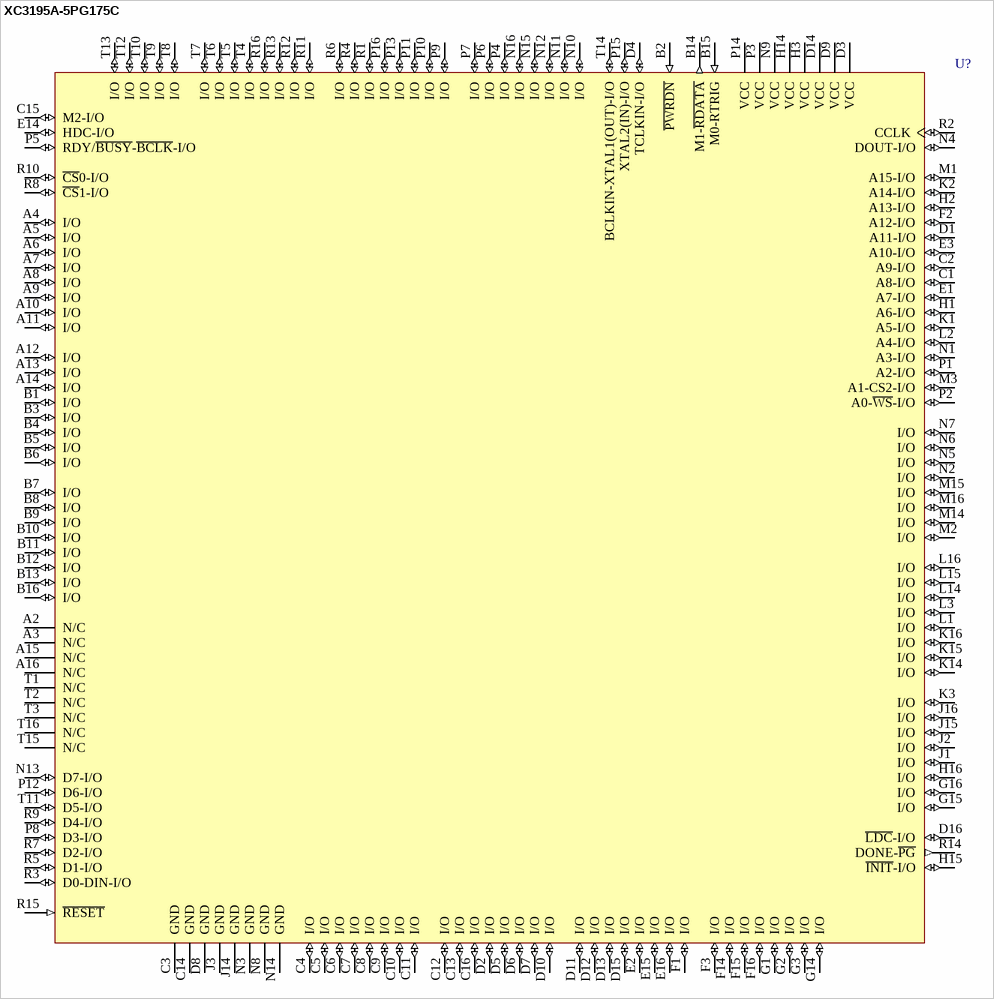
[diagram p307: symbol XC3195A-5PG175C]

## XC3195A-5PG175C
designator U?
Logic Cell Array with 484 CLBs, with 144 I/O Pins, 175-Pin PGA, Commercial Grade; ComponentAvailability: Not for New Design
footprint PG175 (PGA, 175-Leads, Body 42x42mm, Pitch 2.54mm)
3D model XC3195A-PG175 (175-Pin Ceramic Pin Grid Array (PG175))
pins: A2 N/C, A3 N/C, A4 I/O (io), A5 I/O (io), A6 I/O (io), A7 I/O (io), A8 I/O (io), A9 I/O (io), A10 I/O (io), A11 I/O (io), A12 I/O (io), A13 I/O (io), A14 I/O (io), A15 N/C, A16 N/C, B1 I/O (io), B2 ~{PWRDN} (in), B3 I/O (io), B4 I/O (io), B5 I/O (io), B6 I/O (io), B7 I/O (io), B8 I/O (io), B9 I/O (io), B10 I/O (io), B11 I/O (io), B12 I/O (io), B13 I/O (io), B14 M1-~{RDATA} (out), B15 M0-RTRIG (in), B16 I/O (io), C1 A8-I/O (io), C2 A9-I/O (io), C3 GND (power), C4 I/O (io), C5 I/O (io), C6 I/O (io), C7 I/O (io), C8 I/O (io), C9 I/O (io), C10 I/O (io), C11 I/O (io), C12 I/O (io), C13 I/O (io), C14 GND (power), C15 M2-I/O (io), C16 I/O (io), D1 A11-I/O (io), D2 I/O (io), D3 VCC (power), D4 TCLKIN-I/O (io), D5 I/O (io), D6 I/O (io), D7 I/O (io), D8 GND (power), D9 VCC (power), D10 I/O (io), D11 I/O (io), D12 I/O (io), D13 I/O (io), D14 VCC (power), D15 I/O (io), D16 ~{LDC}-I/O (io), E1 A7-I/O (io), E2 I/O (io), E3 A10-I/O (io), E14 HDC-I/O (io), E15 I/O (io), E16 I/O (io), F1 I/O (io), F2 A12-I/O (io), F3 I/O (io), F14 I/O (io), F15 I/O (io), F16 I/O (io), G1 I/O (io), G2 I/O (io), G3 I/O (io), G14 I/O (io), G15 I/O (io), G16 I/O (io), H1 A6-I/O (io), H2 A13-I/O (io), H3 VCC (power), H14 VCC (power), H15 ~{INIT}-I/O (io), H16 I/O (io), J1 I/O (io), J2 I/O (io), J3 GND (power), J14 GND (power), J15 I/O (io), J16 I/O (io), K1 A5-I/O (io), K2 A14-I/O (io), K3 I/O (io), K14 I/O (io), K15 I/O (io), K16 I/O (io), L1 I/O (io), L2 A4-I/O (io), L3 I/O (io), L14 I/O (io), L15 I/O (io), L16 I/O (io), M1 A15-I/O (io), M2 I/O (io), M3 A1-CS2-I/O (io), M14 I/O (io), M15 I/O (io), M16 I/O (io), N1 A3-I/O (io), N2 I/O (io), N3 GND (power), N4 DOUT-I/O (io), N5 I/O (io), N6 I/O (io), N7 I/O (io), N8 GND (power), N9 VCC (power), N10 I/O (io), N11 I/O (io), N12 I/O (io), N13 D7-I/O (io), N14 GND (power), N15 I/O (io), N16 I/O (io), P1 A2-I/O (io), P2 A0-~{WS}-I/O (io), P3 VCC (power), P4 I/O (io), P5 RDY/~{BUSY}-~{BCLK}-I/O (io), P6 I/O (io), P7 I/O (io), P8 D3-I/O (io), P9 I/O (io), P10 I/O (io), P11 I/O (io), P12 D6-I/O (io), P13 I/O (io), P14 VCC (power), P15 XTAL2(IN)-I/O (io), P16 I/O (io), R1 I/O (io), R2 CCLK (io), R3 D0-DIN-I/O (io), R4 I/O (io), R5 D1-I/O (io), R6 I/O (io), R7 D2-I/O (io), R8 ~{CS}1-I/O (io), R9 D4-I/O (io), R10 ~{CS}0-I/O (io), R11 I/O (io), R12 I/O (io), R13 I/O (io), R14 DONE-~{PG} (out), R15 ~{RESET} (in), R16 I/O (io), T1 N/C, T2 N/C, T3 N/C, T4 I/O (io), T5 I/O (io), T6 I/O (io), T7 I/O (io), T8 I/O (io), T9 I/O (io), T10 I/O (io), T11 D5-I/O (io), T12 I/O (io), T13 I/O (io), T14 BCLKIN-XTAL1(OUT)-I/O (io), T15 N/C, T16 N/C

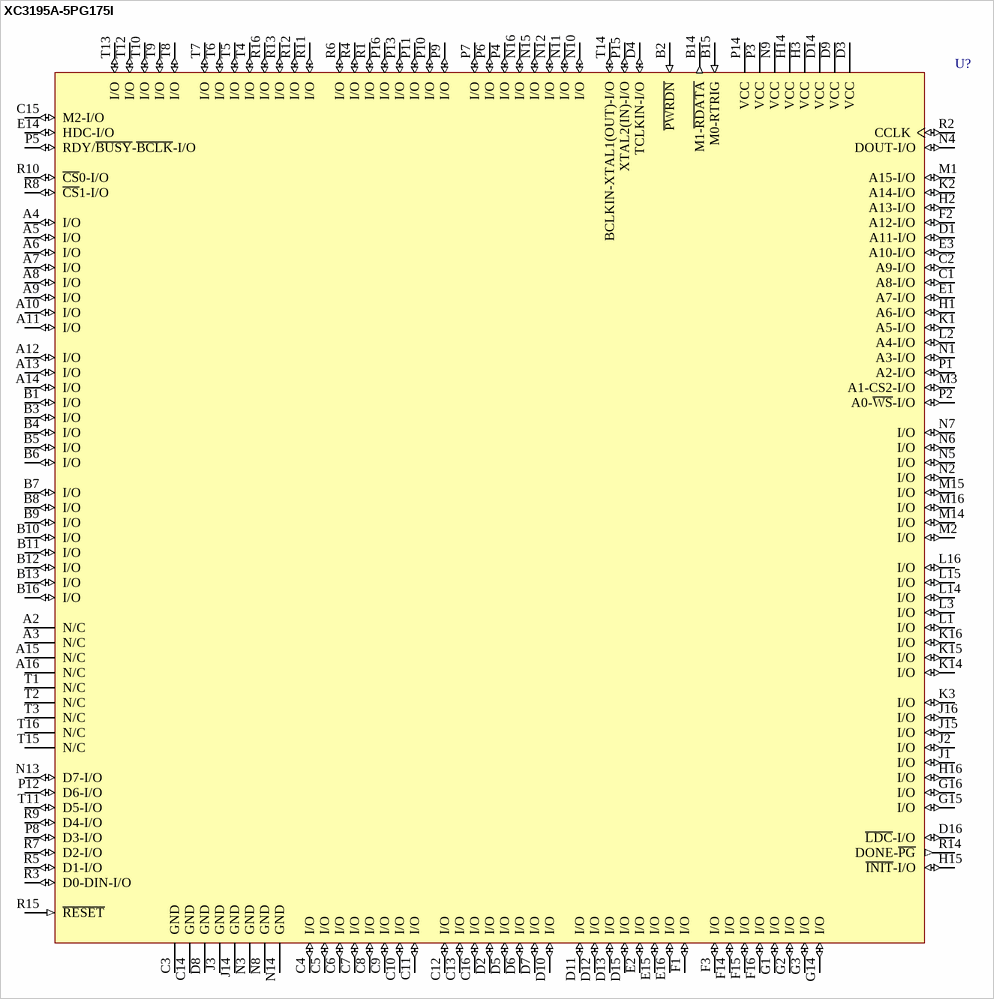
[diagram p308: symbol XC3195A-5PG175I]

## XC3195A-5PG175I
designator U?
Logic Cell Array with 484 CLBs, with 144 I/O Pins, 175-Pin PGA, Industrial Grade; ComponentAvailability: Not for New Design
footprint PG175 (PGA, 175-Leads, Body 42x42mm, Pitch 2.54mm)
3D model XC3195A-PG175 (175-Pin Ceramic Pin Grid Array (PG175))
pins: A2 N/C, A3 N/C, A4 I/O (io), A5 I/O (io), A6 I/O (io), A7 I/O (io), A8 I/O (io), A9 I/O (io), A10 I/O (io), A11 I/O (io), A12 I/O (io), A13 I/O (io), A14 I/O (io), A15 N/C, A16 N/C, B1 I/O (io), B2 ~{PWRDN} (in), B3 I/O (io), B4 I/O (io), B5 I/O (io), B6 I/O (io), B7 I/O (io), B8 I/O (io), B9 I/O (io), B10 I/O (io), B11 I/O (io), B12 I/O (io), B13 I/O (io), B14 M1-~{RDATA} (out), B15 M0-RTRIG (in), B16 I/O (io), C1 A8-I/O (io), C2 A9-I/O (io), C3 GND (power), C4 I/O (io), C5 I/O (io), C6 I/O (io), C7 I/O (io), C8 I/O (io), C9 I/O (io), C10 I/O (io), C11 I/O (io), C12 I/O (io), C13 I/O (io), C14 GND (power), C15 M2-I/O (io), C16 I/O (io), D1 A11-I/O (io), D2 I/O (io), D3 VCC (power), D4 TCLKIN-I/O (io), D5 I/O (io), D6 I/O (io), D7 I/O (io), D8 GND (power), D9 VCC (power), D10 I/O (io), D11 I/O (io), D12 I/O (io), D13 I/O (io), D14 VCC (power), D15 I/O (io), D16 ~{LDC}-I/O (io), E1 A7-I/O (io), E2 I/O (io), E3 A10-I/O (io), E14 HDC-I/O (io), E15 I/O (io), E16 I/O (io), F1 I/O (io), F2 A12-I/O (io), F3 I/O (io), F14 I/O (io), F15 I/O (io), F16 I/O (io), G1 I/O (io), G2 I/O (io), G3 I/O (io), G14 I/O (io), G15 I/O (io), G16 I/O (io), H1 A6-I/O (io), H2 A13-I/O (io), H3 VCC (power), H14 VCC (power), H15 ~{INIT}-I/O (io), H16 I/O (io), J1 I/O (io), J2 I/O (io), J3 GND (power), J14 GND (power), J15 I/O (io), J16 I/O (io), K1 A5-I/O (io), K2 A14-I/O (io), K3 I/O (io), K14 I/O (io), K15 I/O (io), K16 I/O (io), L1 I/O (io), L2 A4-I/O (io), L3 I/O (io), L14 I/O (io), L15 I/O (io), L16 I/O (io), M1 A15-I/O (io), M2 I/O (io), M3 A1-CS2-I/O (io), M14 I/O (io), M15 I/O (io), M16 I/O (io), N1 A3-I/O (io), N2 I/O (io), N3 GND (power), N4 DOUT-I/O (io), N5 I/O (io), N6 I/O (io), N7 I/O (io), N8 GND (power), N9 VCC (power), N10 I/O (io), N11 I/O (io), N12 I/O (io), N13 D7-I/O (io), N14 GND (power), N15 I/O (io), N16 I/O (io), P1 A2-I/O (io), P2 A0-~{WS}-I/O (io), P3 VCC (power), P4 I/O (io), P5 RDY/~{BUSY}-~{BCLK}-I/O (io), P6 I/O (io), P7 I/O (io), P8 D3-I/O (io), P9 I/O (io), P10 I/O (io), P11 I/O (io), P12 D6-I/O (io), P13 I/O (io), P14 VCC (power), P15 XTAL2(IN)-I/O (io), P16 I/O (io), R1 I/O (io), R2 CCLK (io), R3 D0-DIN-I/O (io), R4 I/O (io), R5 D1-I/O (io), R6 I/O (io), R7 D2-I/O (io), R8 ~{CS}1-I/O (io), R9 D4-I/O (io), R10 ~{CS}0-I/O (io), R11 I/O (io), R12 I/O (io), R13 I/O (io), R14 DONE-~{PG} (out), R15 ~{RESET} (in), R16 I/O (io), T1 N/C, T2 N/C, T3 N/C, T4 I/O (io), T5 I/O (io), T6 I/O (io), T7 I/O (io), T8 I/O (io), T9 I/O (io), T10 I/O (io), T11 D5-I/O (io), T12 I/O (io), T13 I/O (io), T14 BCLKIN-XTAL1(OUT)-I/O (io), T15 N/C, T16 N/C

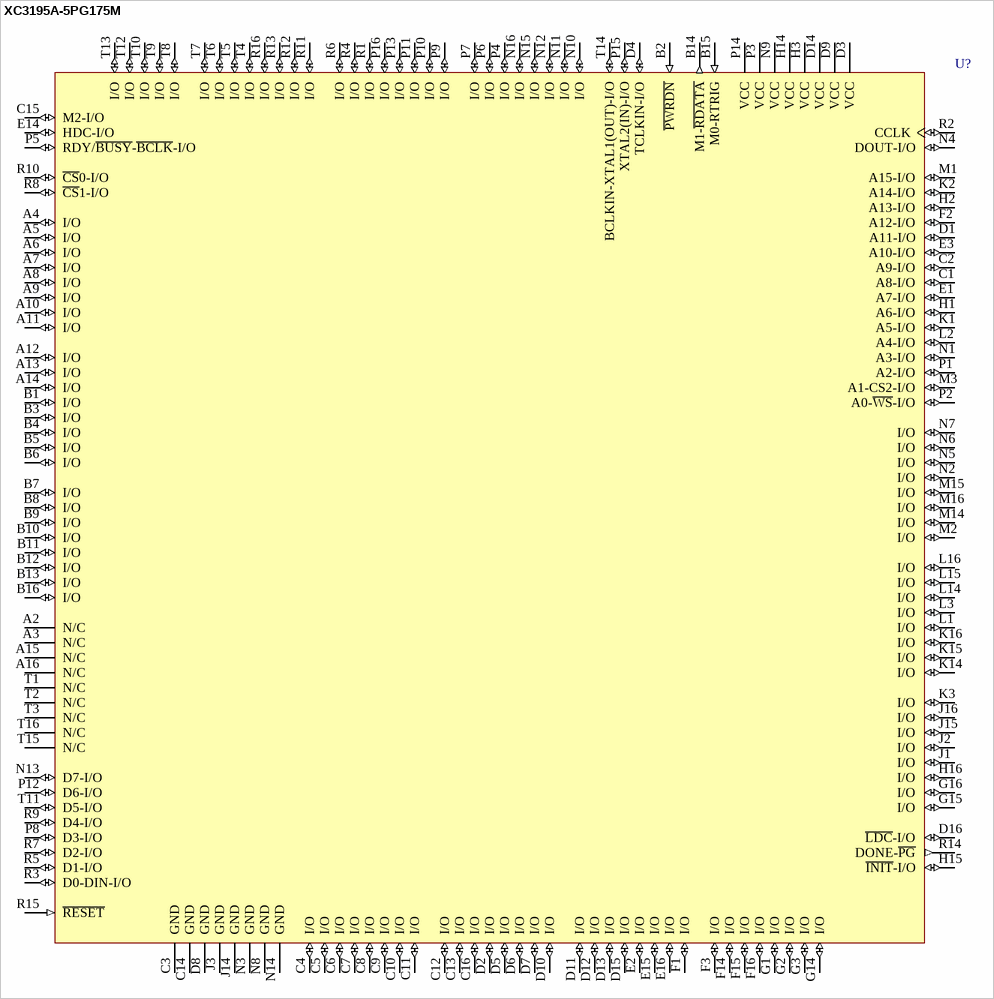
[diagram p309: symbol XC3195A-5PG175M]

## XC3195A-5PG175M
designator U?
Logic Cell Array with 484 CLBs, with 144 I/O Pins, 175-Pin PGA, Military Grade; ComponentAvailability: Not for New Design
footprint PG175 (PGA, 175-Leads, Body 42x42mm, Pitch 2.54mm)
3D model XC3195A-PG175 (175-Pin Ceramic Pin Grid Array (PG175))
pins: A2 N/C, A3 N/C, A4 I/O (io), A5 I/O (io), A6 I/O (io), A7 I/O (io), A8 I/O (io), A9 I/O (io), A10 I/O (io), A11 I/O (io), A12 I/O (io), A13 I/O (io), A14 I/O (io), A15 N/C, A16 N/C, B1 I/O (io), B2 ~{PWRDN} (in), B3 I/O (io), B4 I/O (io), B5 I/O (io), B6 I/O (io), B7 I/O (io), B8 I/O (io), B9 I/O (io), B10 I/O (io), B11 I/O (io), B12 I/O (io), B13 I/O (io), B14 M1-~{RDATA} (out), B15 M0-RTRIG (in), B16 I/O (io), C1 A8-I/O (io), C2 A9-I/O (io), C3 GND (power), C4 I/O (io), C5 I/O (io), C6 I/O (io), C7 I/O (io), C8 I/O (io), C9 I/O (io), C10 I/O (io), C11 I/O (io), C12 I/O (io), C13 I/O (io), C14 GND (power), C15 M2-I/O (io), C16 I/O (io), D1 A11-I/O (io), D2 I/O (io), D3 VCC (power), D4 TCLKIN-I/O (io), D5 I/O (io), D6 I/O (io), D7 I/O (io), D8 GND (power), D9 VCC (power), D10 I/O (io), D11 I/O (io), D12 I/O (io), D13 I/O (io), D14 VCC (power), D15 I/O (io), D16 ~{LDC}-I/O (io), E1 A7-I/O (io), E2 I/O (io), E3 A10-I/O (io), E14 HDC-I/O (io), E15 I/O (io), E16 I/O (io), F1 I/O (io), F2 A12-I/O (io), F3 I/O (io), F14 I/O (io), F15 I/O (io), F16 I/O (io), G1 I/O (io), G2 I/O (io), G3 I/O (io), G14 I/O (io), G15 I/O (io), G16 I/O (io), H1 A6-I/O (io), H2 A13-I/O (io), H3 VCC (power), H14 VCC (power), H15 ~{INIT}-I/O (io), H16 I/O (io), J1 I/O (io), J2 I/O (io), J3 GND (power), J14 GND (power), J15 I/O (io), J16 I/O (io), K1 A5-I/O (io), K2 A14-I/O (io), K3 I/O (io), K14 I/O (io), K15 I/O (io), K16 I/O (io), L1 I/O (io), L2 A4-I/O (io), L3 I/O (io), L14 I/O (io), L15 I/O (io), L16 I/O (io), M1 A15-I/O (io), M2 I/O (io), M3 A1-CS2-I/O (io), M14 I/O (io), M15 I/O (io), M16 I/O (io), N1 A3-I/O (io), N2 I/O (io), N3 GND (power), N4 DOUT-I/O (io), N5 I/O (io), N6 I/O (io), N7 I/O (io), N8 GND (power), N9 VCC (power), N10 I/O (io), N11 I/O (io), N12 I/O (io), N13 D7-I/O (io), N14 GND (power), N15 I/O (io), N16 I/O (io), P1 A2-I/O (io), P2 A0-~{WS}-I/O (io), P3 VCC (power), P4 I/O (io), P5 RDY/~{BUSY}-~{BCLK}-I/O (io), P6 I/O (io), P7 I/O (io), P8 D3-I/O (io), P9 I/O (io), P10 I/O (io), P11 I/O (io), P12 D6-I/O (io), P13 I/O (io), P14 VCC (power), P15 XTAL2(IN)-I/O (io), P16 I/O (io), R1 I/O (io), R2 CCLK (io), R3 D0-DIN-I/O (io), R4 I/O (io), R5 D1-I/O (io), R6 I/O (io), R7 D2-I/O (io), R8 ~{CS}1-I/O (io), R9 D4-I/O (io), R10 ~{CS}0-I/O (io), R11 I/O (io), R12 I/O (io), R13 I/O (io), R14 DONE-~{PG} (out), R15 ~{RESET} (in), R16 I/O (io), T1 N/C, T2 N/C, T3 N/C, T4 I/O (io), T5 I/O (io), T6 I/O (io), T7 I/O (io), T8 I/O (io), T9 I/O (io), T10 I/O (io), T11 D5-I/O (io), T12 I/O (io), T13 I/O (io), T14 BCLKIN-XTAL1(OUT)-I/O (io), T15 N/C, T16 N/C

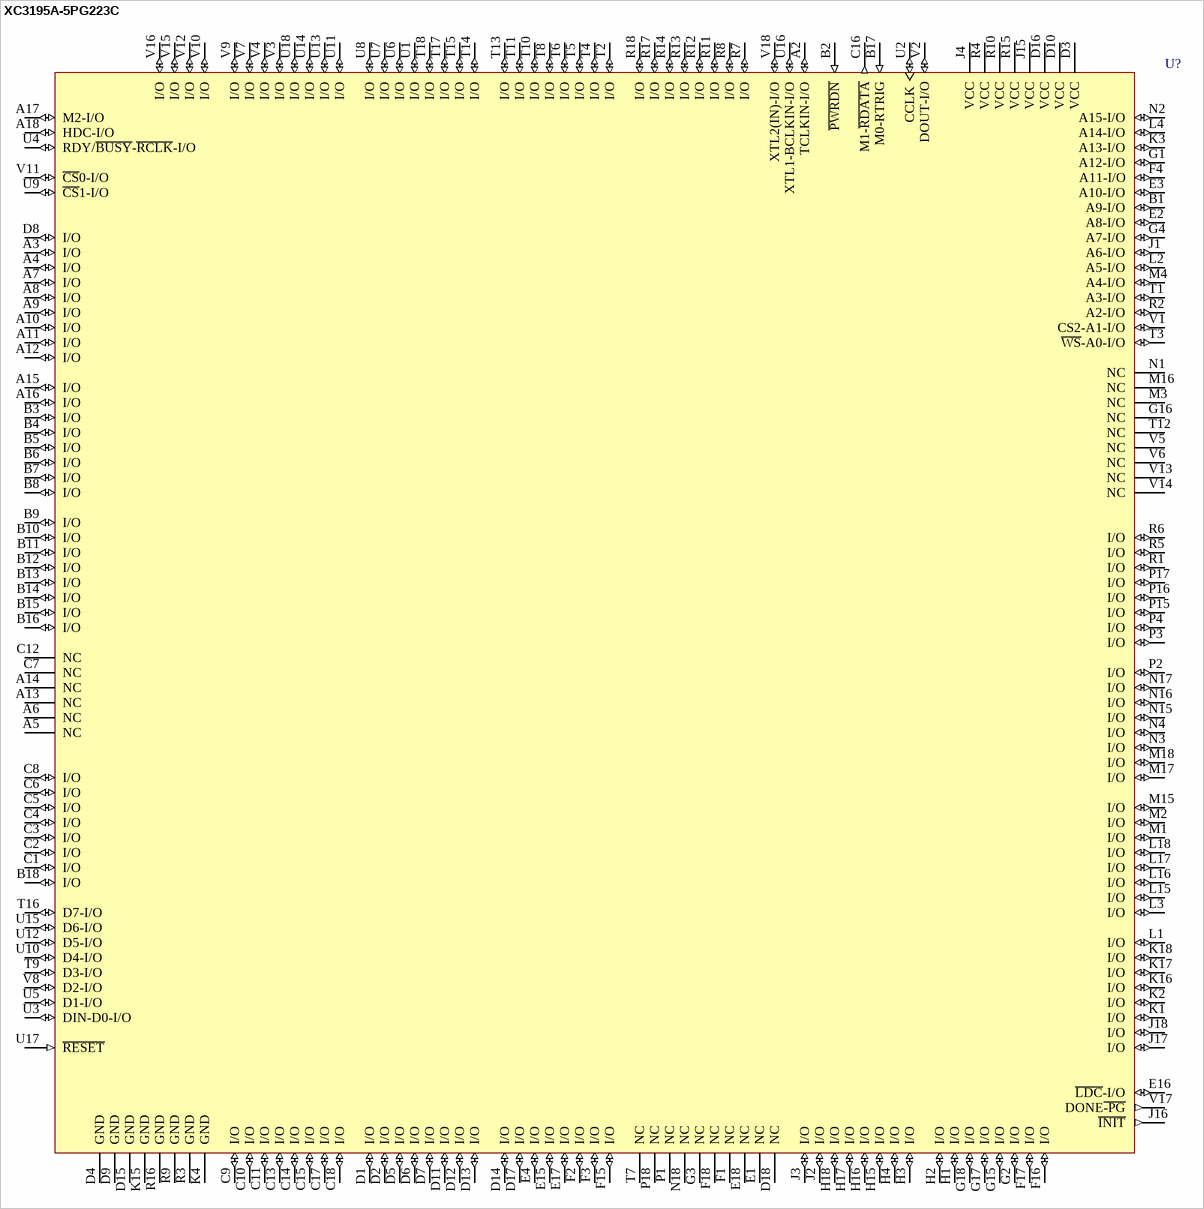
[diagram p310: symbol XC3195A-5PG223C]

## XC3195A-5PG223C
designator U?
Logic Cell Array with 484 CLBs, with 174 I/O Pins, 223-Pin PGA, Commercial Grade; ComponentAvailability: Not for New Design
footprint PG223 (PGA, 223-Leads, Body 47x47mm, Pitch 2.54mm)
3D model XC3195A-PG223 (223-Pin Ceramic Pin Grid Array (PG223))
pins: A2 TCLKIN-I/O (io), A3 I/O (io), A4 I/O (io), A5 NC, A6 NC, A7 I/O (io), A8 I/O (io), A9 I/O (io), A10 I/O (io), A11 I/O (io), A12 I/O (io), A13 NC, A14 NC, A15 I/O (io), A16 I/O (io), A17 M2-I/O (io), A18 HDC-I/O (io), B1 A9-I/O (io), B2 ~{PWRDN} (in), B3 I/O (io), B4 I/O (io), B5 I/O (io), B6 I/O (io), B7 I/O (io), B8 I/O (io), B9 I/O (io), B10 I/O (io), B11 I/O (io), B12 I/O (io), B13 I/O (io), B14 I/O (io), B15 I/O (io), B16 I/O (io), B17 M0-RTRIG (in), B18 I/O (io), C1 I/O (io), C2 I/O (io), C3 I/O (io), C4 I/O (io), C5 I/O (io), C6 I/O (io), C7 NC, C8 I/O (io), C9 I/O (io), C10 I/O (io), C11 I/O (io), C12 NC, C13 I/O (io), C14 I/O (io), C15 I/O (io), C16 M1-~{RDATA} (out), C17 I/O (io), C18 I/O (io), D1 I/O (io), D2 I/O (io), D3 VCC (power), D4 GND (power), D5 I/O (io), D6 I/O (io), D7 I/O (io), D8 I/O (io), D9 GND (power), D10 VCC (power), D11 I/O (io), D12 I/O (io), D13 I/O (io), D14 I/O (io), D15 GND (power), D16 VCC (power), D17 I/O (io), D18 NC, E1 NC, E2 A8-I/O (io), E3 A10-I/O (io), E4 I/O (io), E15 I/O (io), E16 ~{LDC}-I/O (io), E17 I/O (io), E18 NC, F1 NC, F2 I/O (io), F3 I/O (io), F4 A11-I/O (io), F15 I/O (io), F16 I/O (io), F17 I/O (io), F18 NC, G1 A12-I/O (io), G2 I/O (io), G3 NC, G4 A7-I/O (io), G15 I/O (io), G16 NC, G17 I/O (io), G18 I/O (io), H1 I/O (io), H2 I/O (io), H3 I/O (io), H4 I/O (io), H15 I/O (io), H16 I/O (io), H17 I/O (io), H18 I/O (io), J1 A6-I/O (io), J2 I/O (io), J3 I/O (io), J4 VCC (power), J15 VCC (power), J16 ~{INIT} (out), J17 I/O (io), J18 I/O (io), K1 I/O (io), K2 I/O (io), K3 A13-I/O (io), K4 GND (power), K15 GND (power), K16 I/O (io), K17 I/O (io), K18 I/O (io), L1 I/O (io), L2 A5-I/O (io), L3 I/O (io), L4 A14-I/O (io), L15 I/O (io), L16 I/O (io), L17 I/O (io), L18 I/O (io), M1 I/O (io), M2 I/O (io), M3 NC, M4 A4-I/O (io), M15 I/O (io), M16 NC, M17 I/O (io), M18 I/O (io), N1 NC, N2 A15-I/O (io), N3 I/O (io), N4 I/O (io), N15 I/O (io), N16 I/O (io), N17 I/O (io), N18 NC, P1 NC, P2 I/O (io), P3 I/O (io), P4 I/O (io), P15 I/O (io), P16 I/O (io), P17 I/O (io), P18 NC, R1 I/O (io), R2 A2-I/O (io), R3 GND (power), R4 VCC (power), R5 I/O (io), R6 I/O (io), R7 I/O (io), R8 I/O (io), R9 GND (power), R10 VCC (power), R11 I/O (io), R12 I/O (io), R13 I/O (io), R14 I/O (io), R15 VCC (power), R16 GND (power), R17 I/O (io), R18 I/O (io), T1 A3-I/O (io), T2 I/O (io), T3 ~{WS}-A0-I/O (io), T4 I/O (io), T5 I/O (io), T6 I/O (io), T7 NC, T8 I/O (io), T9 D3-I/O (io), T10 I/O (io), T11 I/O (io), T12 NC, T13 I/O (io), T14 I/O (io), T15 I/O (io), T16 D7-I/O (io), T17 I/O (io), T18 I/O (io), U1 I/O (io), U2 CCLK (io), U3 DIN-D0-I/O (io), U4 RDY/~{BUSY}-~{RCLK}-I/O (io), U5 D1-I/O (io), U6 I/O (io), U7 I/O (io), U8 I/O (io), U9 ~{CS}1-I/O (io), U10 D4-I/O (io), U11 I/O (io), U12 D5-I/O (io), U13 I/O (io), U14 I/O (io), U15 D6-I/O (io), U16 XTL1-BCLKIN-I/O (io), U17 ~{RESET} (in), U18 I/O (io), V1 CS2-A1-I/O (io), V2 DOUT-I/O (io), V3 I/O (io), V4 I/O (io), V5 NC, V6 NC, V7 I/O (io), V8 D2-I/O (io), V9 I/O (io), V10 I/O (io), V11 ~{CS}0-I/O (io), V12 I/O (io), V13 NC, V14 NC, V15 I/O (io), V16 I/O (io), V17 DONE~{-PG} (out), V18 XTL2(IN)-I/O (io)

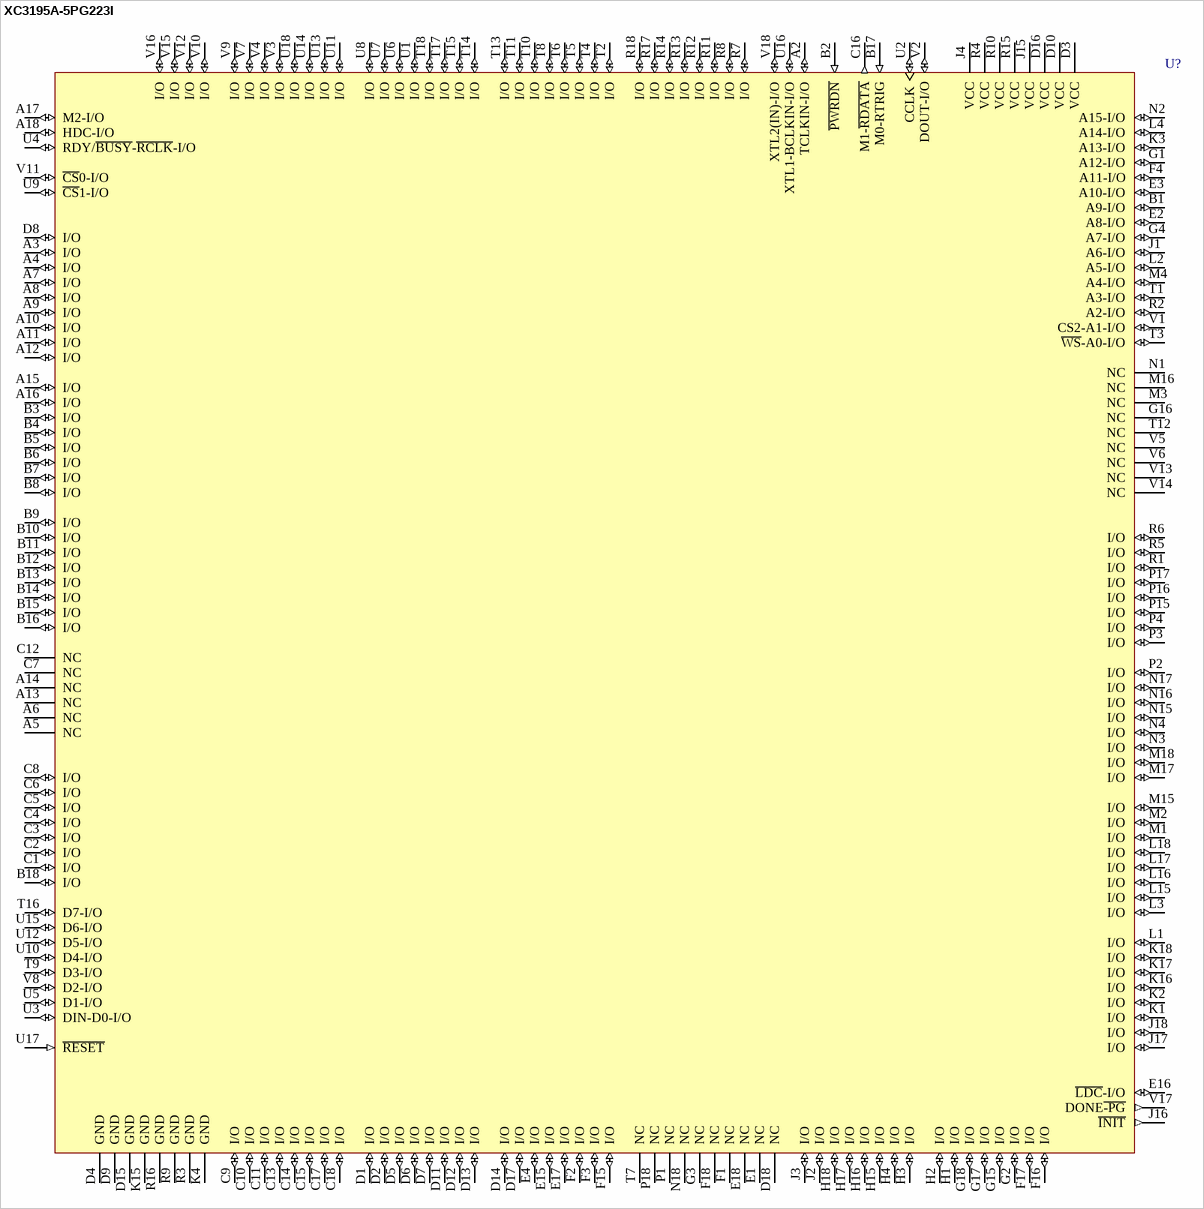
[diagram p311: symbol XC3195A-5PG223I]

## XC3195A-5PG223I
designator U?
Logic Cell Array with 484 CLBs, with 174 I/O Pins, 223-Pin PGA, Industrial Grade; ComponentAvailability: Not for New Design
footprint PG223 (PGA, 223-Leads, Body 47x47mm, Pitch 2.54mm)
3D model XC3195A-PG223 (223-Pin Ceramic Pin Grid Array (PG223))
pins: A2 TCLKIN-I/O (io), A3 I/O (io), A4 I/O (io), A5 NC, A6 NC, A7 I/O (io), A8 I/O (io), A9 I/O (io), A10 I/O (io), A11 I/O (io), A12 I/O (io), A13 NC, A14 NC, A15 I/O (io), A16 I/O (io), A17 M2-I/O (io), A18 HDC-I/O (io), B1 A9-I/O (io), B2 ~{PWRDN} (in), B3 I/O (io), B4 I/O (io), B5 I/O (io), B6 I/O (io), B7 I/O (io), B8 I/O (io), B9 I/O (io), B10 I/O (io), B11 I/O (io), B12 I/O (io), B13 I/O (io), B14 I/O (io), B15 I/O (io), B16 I/O (io), B17 M0-RTRIG (in), B18 I/O (io), C1 I/O (io), C2 I/O (io), C3 I/O (io), C4 I/O (io), C5 I/O (io), C6 I/O (io), C7 NC, C8 I/O (io), C9 I/O (io), C10 I/O (io), C11 I/O (io), C12 NC, C13 I/O (io), C14 I/O (io), C15 I/O (io), C16 M1-~{RDATA} (out), C17 I/O (io), C18 I/O (io), D1 I/O (io), D2 I/O (io), D3 VCC (power), D4 GND (power), D5 I/O (io), D6 I/O (io), D7 I/O (io), D8 I/O (io), D9 GND (power), D10 VCC (power), D11 I/O (io), D12 I/O (io), D13 I/O (io), D14 I/O (io), D15 GND (power), D16 VCC (power), D17 I/O (io), D18 NC, E1 NC, E2 A8-I/O (io), E3 A10-I/O (io), E4 I/O (io), E15 I/O (io), E16 ~{LDC}-I/O (io), E17 I/O (io), E18 NC, F1 NC, F2 I/O (io), F3 I/O (io), F4 A11-I/O (io), F15 I/O (io), F16 I/O (io), F17 I/O (io), F18 NC, G1 A12-I/O (io), G2 I/O (io), G3 NC, G4 A7-I/O (io), G15 I/O (io), G16 NC, G17 I/O (io), G18 I/O (io), H1 I/O (io), H2 I/O (io), H3 I/O (io), H4 I/O (io), H15 I/O (io), H16 I/O (io), H17 I/O (io), H18 I/O (io), J1 A6-I/O (io), J2 I/O (io), J3 I/O (io), J4 VCC (power), J15 VCC (power), J16 ~{INIT} (out), J17 I/O (io), J18 I/O (io), K1 I/O (io), K2 I/O (io), K3 A13-I/O (io), K4 GND (power), K15 GND (power), K16 I/O (io), K17 I/O (io), K18 I/O (io), L1 I/O (io), L2 A5-I/O (io), L3 I/O (io), L4 A14-I/O (io), L15 I/O (io), L16 I/O (io), L17 I/O (io), L18 I/O (io), M1 I/O (io), M2 I/O (io), M3 NC, M4 A4-I/O (io), M15 I/O (io), M16 NC, M17 I/O (io), M18 I/O (io), N1 NC, N2 A15-I/O (io), N3 I/O (io), N4 I/O (io), N15 I/O (io), N16 I/O (io), N17 I/O (io), N18 NC, P1 NC, P2 I/O (io), P3 I/O (io), P4 I/O (io), P15 I/O (io), P16 I/O (io), P17 I/O (io), P18 NC, R1 I/O (io), R2 A2-I/O (io), R3 GND (power), R4 VCC (power), R5 I/O (io), R6 I/O (io), R7 I/O (io), R8 I/O (io), R9 GND (power), R10 VCC (power), R11 I/O (io), R12 I/O (io), R13 I/O (io), R14 I/O (io), R15 VCC (power), R16 GND (power), R17 I/O (io), R18 I/O (io), T1 A3-I/O (io), T2 I/O (io), T3 ~{WS}-A0-I/O (io), T4 I/O (io), T5 I/O (io), T6 I/O (io), T7 NC, T8 I/O (io), T9 D3-I/O (io), T10 I/O (io), T11 I/O (io), T12 NC, T13 I/O (io), T14 I/O (io), T15 I/O (io), T16 D7-I/O (io), T17 I/O (io), T18 I/O (io), U1 I/O (io), U2 CCLK (io), U3 DIN-D0-I/O (io), U4 RDY/~{BUSY}-~{RCLK}-I/O (io), U5 D1-I/O (io), U6 I/O (io), U7 I/O (io), U8 I/O (io), U9 ~{CS}1-I/O (io), U10 D4-I/O (io), U11 I/O (io), U12 D5-I/O (io), U13 I/O (io), U14 I/O (io), U15 D6-I/O (io), U16 XTL1-BCLKIN-I/O (io), U17 ~{RESET} (in), U18 I/O (io), V1 CS2-A1-I/O (io), V2 DOUT-I/O (io), V3 I/O (io), V4 I/O (io), V5 NC, V6 NC, V7 I/O (io), V8 D2-I/O (io), V9 I/O (io), V10 I/O (io), V11 ~{CS}0-I/O (io), V12 I/O (io), V13 NC, V14 NC, V15 I/O (io), V16 I/O (io), V17 DONE~{-PG} (out), V18 XTL2(IN)-I/O (io)

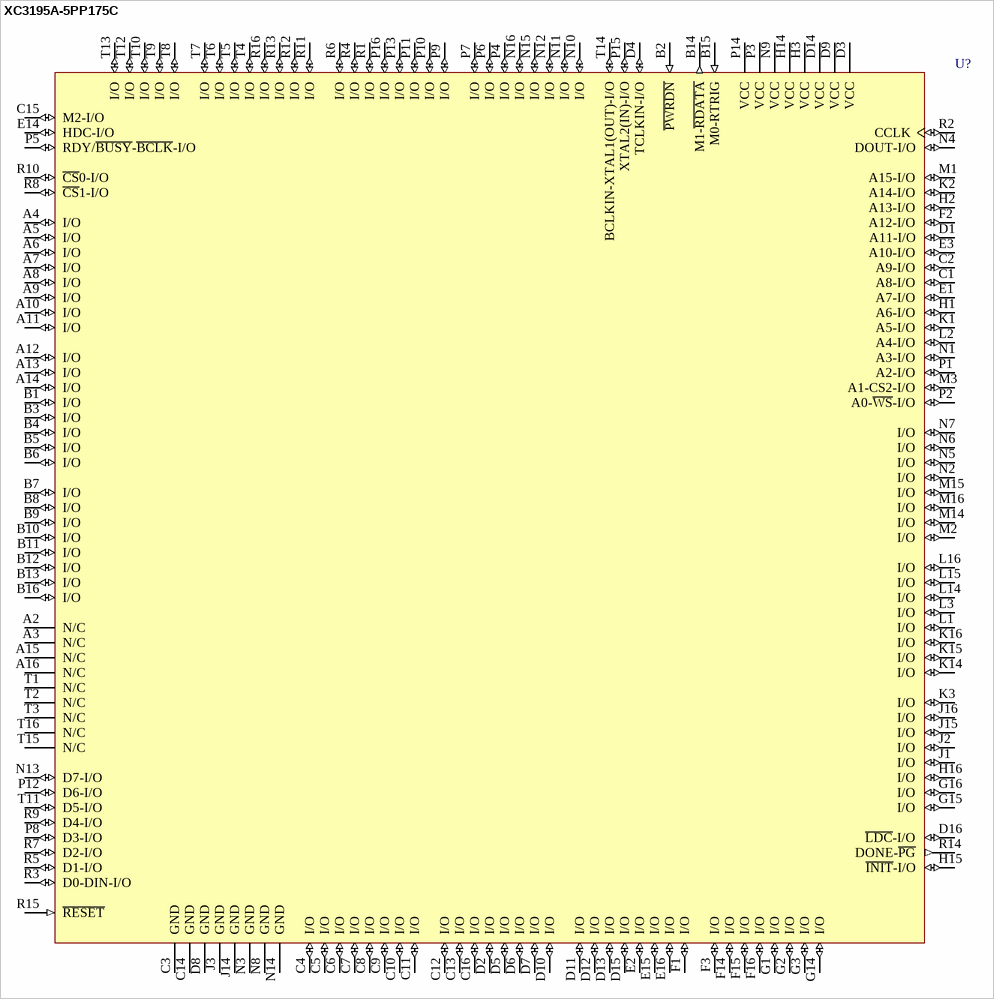
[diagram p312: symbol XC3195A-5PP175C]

## XC3195A-5PP175C
designator U?
Logic Cell Array with 484 CLBs, with 144 I/O Pins, 175-Pin PGA, Commercial Grade; ComponentAvailability: Not for New Design
footprint PP175 (PGA, 175-Leads, Body 42x42mm, Pitch 2.54mm)
3D model XC3195A-PP175 (175-Pin Plastic Pin Grid Array (PP175))
pins: A2 N/C, A3 N/C, A4 I/O (io), A5 I/O (io), A6 I/O (io), A7 I/O (io), A8 I/O (io), A9 I/O (io), A10 I/O (io), A11 I/O (io), A12 I/O (io), A13 I/O (io), A14 I/O (io), A15 N/C, A16 N/C, B1 I/O (io), B2 ~{PWRDN} (in), B3 I/O (io), B4 I/O (io), B5 I/O (io), B6 I/O (io), B7 I/O (io), B8 I/O (io), B9 I/O (io), B10 I/O (io), B11 I/O (io), B12 I/O (io), B13 I/O (io), B14 M1-~{RDATA} (out), B15 M0-RTRIG (in), B16 I/O (io), C1 A8-I/O (io), C2 A9-I/O (io), C3 GND (power), C4 I/O (io), C5 I/O (io), C6 I/O (io), C7 I/O (io), C8 I/O (io), C9 I/O (io), C10 I/O (io), C11 I/O (io), C12 I/O (io), C13 I/O (io), C14 GND (power), C15 M2-I/O (io), C16 I/O (io), D1 A11-I/O (io), D2 I/O (io), D3 VCC (power), D4 TCLKIN-I/O (io), D5 I/O (io), D6 I/O (io), D7 I/O (io), D8 GND (power), D9 VCC (power), D10 I/O (io), D11 I/O (io), D12 I/O (io), D13 I/O (io), D14 VCC (power), D15 I/O (io), D16 ~{LDC}-I/O (io), E1 A7-I/O (io), E2 I/O (io), E3 A10-I/O (io), E14 HDC-I/O (io), E15 I/O (io), E16 I/O (io), F1 I/O (io), F2 A12-I/O (io), F3 I/O (io), F14 I/O (io), F15 I/O (io), F16 I/O (io), G1 I/O (io), G2 I/O (io), G3 I/O (io), G14 I/O (io), G15 I/O (io), G16 I/O (io), H1 A6-I/O (io), H2 A13-I/O (io), H3 VCC (power), H14 VCC (power), H15 ~{INIT}-I/O (io), H16 I/O (io), J1 I/O (io), J2 I/O (io), J3 GND (power), J14 GND (power), J15 I/O (io), J16 I/O (io), K1 A5-I/O (io), K2 A14-I/O (io), K3 I/O (io), K14 I/O (io), K15 I/O (io), K16 I/O (io), L1 I/O (io), L2 A4-I/O (io), L3 I/O (io), L14 I/O (io), L15 I/O (io), L16 I/O (io), M1 A15-I/O (io), M2 I/O (io), M3 A1-CS2-I/O (io), M14 I/O (io), M15 I/O (io), M16 I/O (io), N1 A3-I/O (io), N2 I/O (io), N3 GND (power), N4 DOUT-I/O (io), N5 I/O (io), N6 I/O (io), N7 I/O (io), N8 GND (power), N9 VCC (power), N10 I/O (io), N11 I/O (io), N12 I/O (io), N13 D7-I/O (io), N14 GND (power), N15 I/O (io), N16 I/O (io), P1 A2-I/O (io), P2 A0-~{WS}-I/O (io), P3 VCC (power), P4 I/O (io), P5 RDY/~{BUSY}-~{BCLK}-I/O (io), P6 I/O (io), P7 I/O (io), P8 D3-I/O (io), P9 I/O (io), P10 I/O (io), P11 I/O (io), P12 D6-I/O (io), P13 I/O (io), P14 VCC (power), P15 XTAL2(IN)-I/O (io), P16 I/O (io), R1 I/O (io), R2 CCLK (io), R3 D0-DIN-I/O (io), R4 I/O (io), R5 D1-I/O (io), R6 I/O (io), R7 D2-I/O (io), R8 ~{CS}1-I/O (io), R9 D4-I/O (io), R10 ~{CS}0-I/O (io), R11 I/O (io), R12 I/O (io), R13 I/O (io), R14 DONE-~{PG} (out), R15 ~{RESET} (in), R16 I/O (io), T1 N/C, T2 N/C, T3 N/C, T4 I/O (io), T5 I/O (io), T6 I/O (io), T7 I/O (io), T8 I/O (io), T9 I/O (io), T10 I/O (io), T11 D5-I/O (io), T12 I/O (io), T13 I/O (io), T14 BCLKIN-XTAL1(OUT)-I/O (io), T15 N/C, T16 N/C

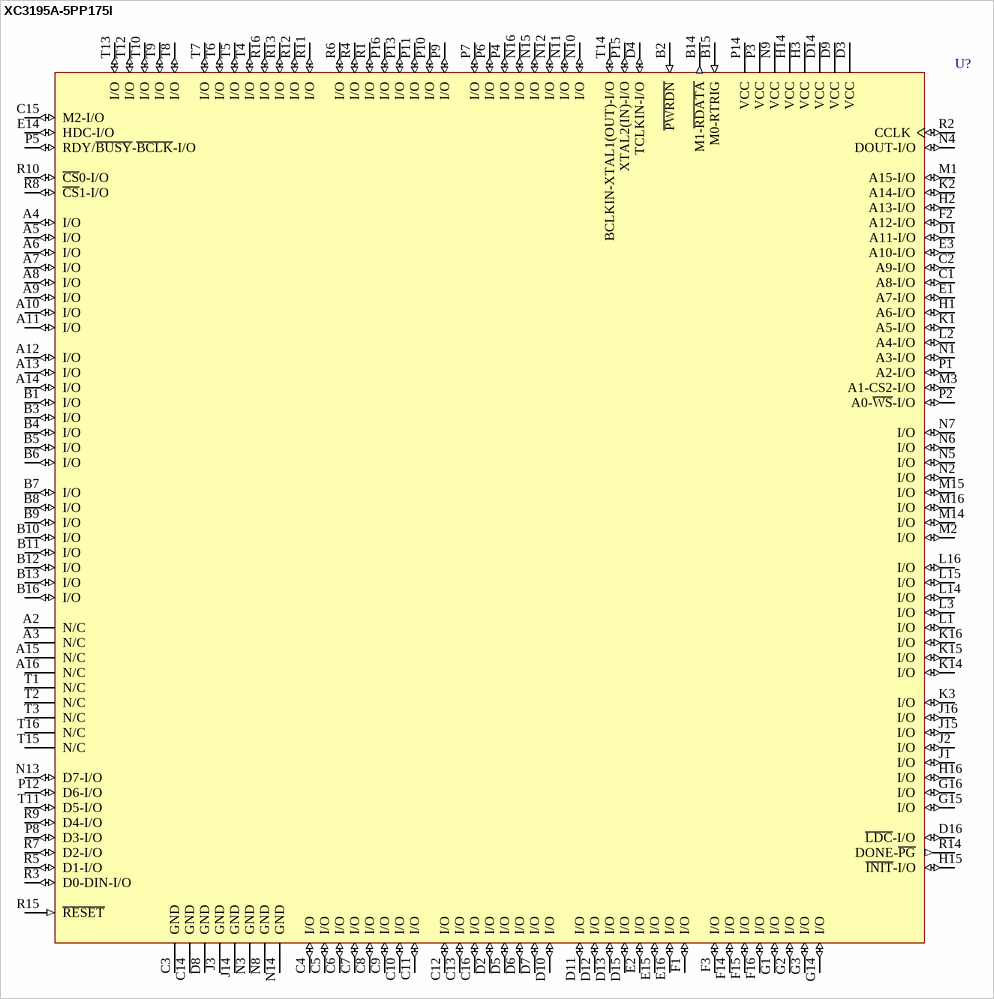
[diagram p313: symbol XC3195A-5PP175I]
